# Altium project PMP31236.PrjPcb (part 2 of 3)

## Sheet PMP31236RevA_LS_U.SchDoc
size 431 x 279 mm; Date: Not shown in title block; ApprovedBy: Not shown in title block; CheckedBy: Not shown in title block; Author: Not shown in title block; CompanyName: Not shown in title block; Engineer: Not shown in title block; Organization: Not shown in title block; Address1: Not shown in title block; Address2: Not shown in title block; Address3: Not shown in title block; Address4: Not shown in title block; DocumentNumber: 4; Revision: Use project parameter SCH_Rev; SheetNumber: 4; SheetTotal: 11; PageSetup: Record=PageOptions¦CenterHorizontal=True¦CenterVertical=True¦PrintScale=1.00¦XCorrection=1.00¦YCorrection=1.00¦PrintKind=0¦BorderSize=5000000¦LeftOffset=0¦BottomOffset=0¦Orientation=2¦PaperLength=1000¦PaperWidth=1000¦Scale=100¦PaperSource=15¦PrintQuality=600¦MediaType=1¦DitherType=10¦PaperKind=Letter¦PrintScaleMode=1
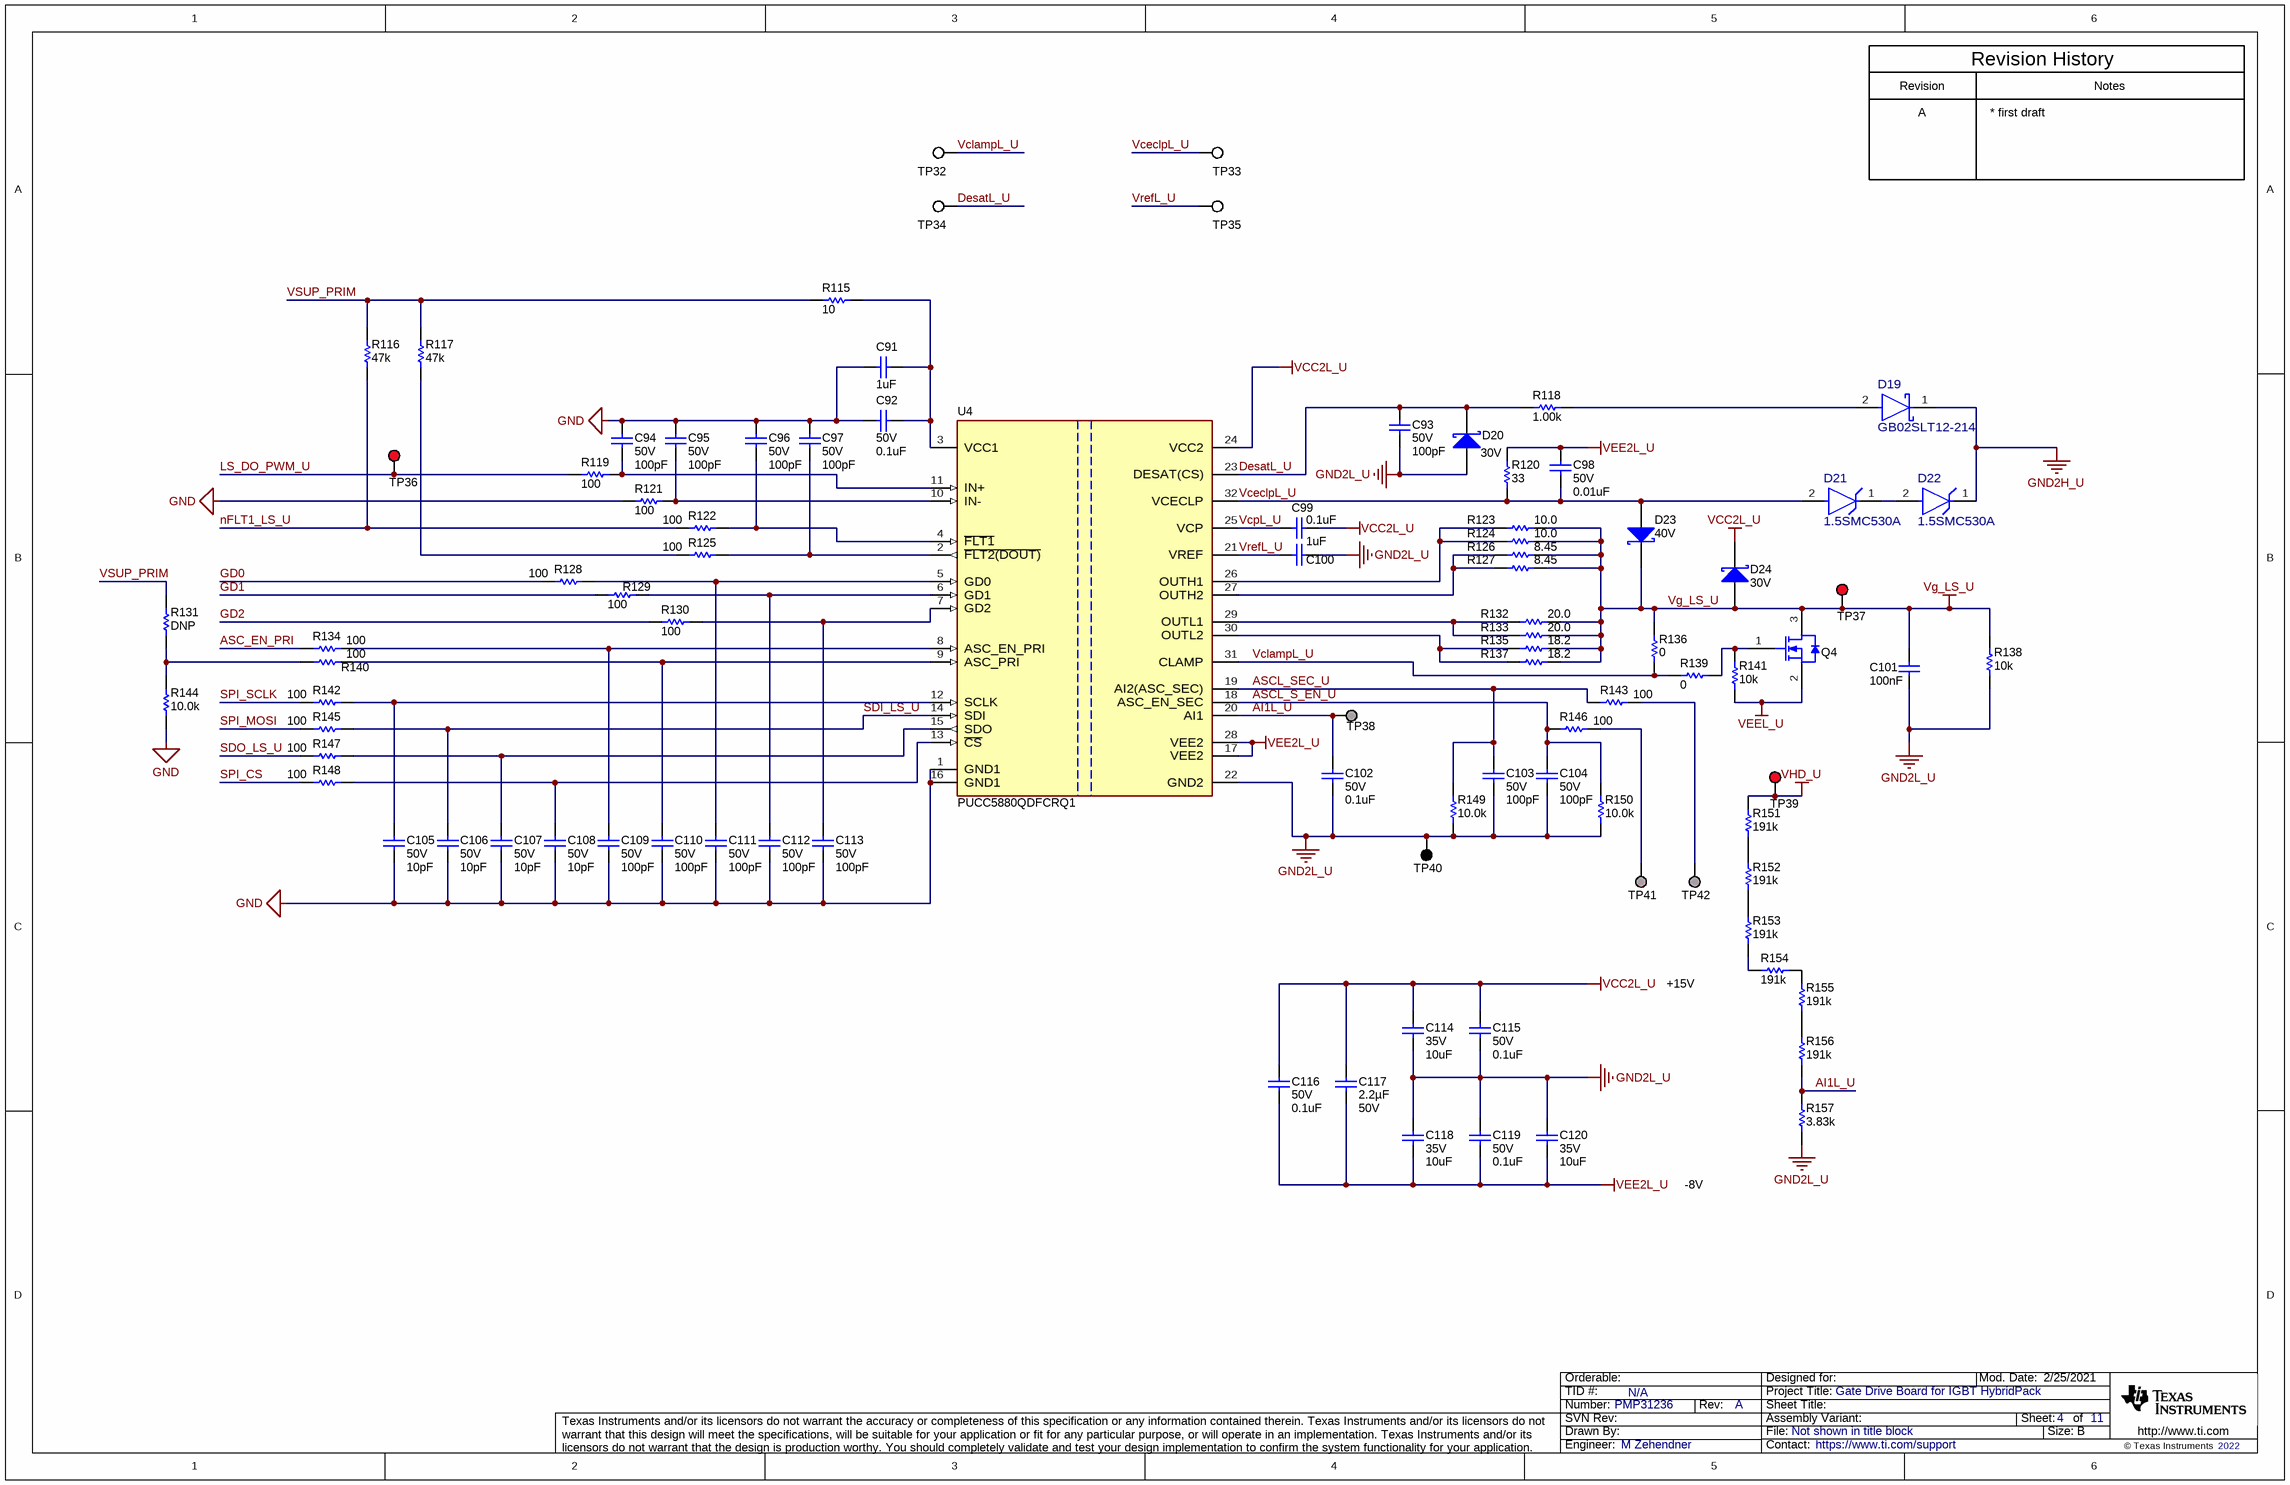
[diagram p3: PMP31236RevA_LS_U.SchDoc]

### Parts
C91  ValueDisplayed: 1uF  [0603]  (hidden comment: GRM21BR72A104KAC4L)
C92  VDC_V: 50V  ValueDisplayed: 0.1uF  [0402]  (hidden comment: GCM155R71H104KE02D)
C93  VDC_V: 50V  ValueDisplayed: 100pF  [0402]  (hidden comment: GRM1555C1H101JA01D)
C94  VDC_V: 50V  ValueDisplayed: 100pF  [0402]  (hidden comment: GRM1555C1H101JA01D)
C95  VDC_V: 50V  ValueDisplayed: 100pF  [0402]  (hidden comment: GRM1555C1H101JA01D)
C96  VDC_V: 50V  ValueDisplayed: 100pF  [0402]  (hidden comment: GRM1555C1H101JA01D)
C97  VDC_V: 50V  ValueDisplayed: 100pF  [0402]  (hidden comment: GRM1555C1H101JA01D)
C98  VDC_V: 50V  ValueDisplayed: 0.01uF  [0402]  (hidden comment: CGA2B3X7R1H103K050BB)
C99  ValueDisplayed: 0.1uF  [0402]  (hidden comment: GCM155R71H104KE02D)
C100  ValueDisplayed: 1uF  [0603]  (hidden comment: CGA3E1X7R1V105K080AC)
C101  Cap_F: 100nF  [0805_HV]  (hidden comment: C0805C104K5RACAUTO)
C102  VDC_V: 50V  ValueDisplayed: 0.1uF  [0402]  (hidden comment: GCM155R71H104KE02D)
C103  VDC_V: 50V  ValueDisplayed: 100pF  [0402]  (hidden comment: GRM1555C1H101JA01D)
C104  VDC_V: 50V  ValueDisplayed: 100pF  [0402]  (hidden comment: GRM1555C1H101JA01D)
C105  VDC_V: 50V  ValueDisplayed: 10pF  [0402]  (hidden comment: GCM1555C1H100JA16D)
C106  VDC_V: 50V  ValueDisplayed: 10pF  [0402]  (hidden comment: GCM1555C1H100JA16D)
C107  VDC_V: 50V  ValueDisplayed: 10pF  [0402]  (hidden comment: GCM1555C1H100JA16D)
C108  VDC_V: 50V  ValueDisplayed: 10pF  [0402]  (hidden comment: GCM1555C1H100JA16D)
C109  VDC_V: 50V  ValueDisplayed: 100pF  [0402]  (hidden comment: GRM1555C1H101JA01D)
C110  VDC_V: 50V  ValueDisplayed: 100pF  [0402]  (hidden comment: GRM1555C1H101JA01D)
C111  VDC_V: 50V  ValueDisplayed: 100pF  [0402]  (hidden comment: GRM1555C1H101JA01D)
C112  VDC_V: 50V  ValueDisplayed: 100pF  [0402]  (hidden comment: GRM1555C1H101JA01D)
C113  VDC_V: 50V  ValueDisplayed: 100pF  [0402]  (hidden comment: GRM1555C1H101JA01D)
C114  VDC_V: 35V  ValueDisplayed: 10uF  [1206_190]  (hidden comment: CGA5L1X7R1V106M160AC)
C115  VDC_V: 50V  ValueDisplayed: 0.1uF  [0402]  (hidden comment: GCM155R71H104KE02D)
C116  VDC_V: 50V  ValueDisplayed: 0.1uF  [0402]  (hidden comment: GCM155R71H104KE02D)
C117  Cap_F: 2.2µF  VDC_V: 50V  [0805_HV]  (hidden comment: CGA4J3X7R1H225K125AB)
C118  VDC_V: 35V  ValueDisplayed: 10uF  [1206_190]  (hidden comment: CGA5L1X7R1V106M160AC)
C119  VDC_V: 50V  ValueDisplayed: 0.1uF  [0402]  (hidden comment: GCM155R71H104KE02D)
C120  VDC_V: 35V  ValueDisplayed: 10uF  [1206_190]  (hidden comment: CGA5L1X7R1V106M160AC)
D19  GB02SLT12-214  [FP-GB02SLT12-214_DO-214AA-MFG]
D20  value 30V  [SOD-323]  (hidden comment: BAT54WS-7-F)
D21  1.5SMC530A  [FP-1.5SMC530A_SMC-MFG]
D22  1.5SMC530A  [FP-1.5SMC530A_SMC-MFG]
D23  value 40V  [SMA]  (hidden comment: MBRA340T3G)
D24  value 30V  [SOD-323]  (hidden comment: BAT54WS-7-F)
Q4  SI2318CDS-T1-GE3  [SOT-23]  (value not drawn)
R115  ValueDisplayed: 10  [0402]  (hidden comment: CRCW040210R0JNED)
R116  ValueDisplayed: 47k  [0402]  (hidden comment: CRCW040247K0JNED)
R117  ValueDisplayed: 47k  [0402]  (hidden comment: CRCW040247K0JNED)
R118  ValueDisplayed: 1.00k  [0603]  (hidden comment: CRCW06031K00FKEA)
R119  ValueDisplayed: 100  [0402]  (hidden comment: CRCW0402100RJNED)
R120  ValueDisplayed: 33  [0603]  (hidden comment: CRCW060333R0JNEA)
R121  ValueDisplayed: 100  [0402]  (hidden comment: CRCW0402100RJNED)
R122  ValueDisplayed: 100  [0402]  (hidden comment: CRCW0402100RJNED)
R123  ValueDisplayed: 10.0  [0805_HV]  (hidden comment: CRCW080510R0FKEA)
R124  ValueDisplayed: 10.0  [0805_HV]  (hidden comment: CRCW080510R0FKEA)
R125  ValueDisplayed: 100  [0402]  (hidden comment: CRCW0402100RJNED)
R126  ValueDisplayed: 8.45  [0805_HV]  (hidden comment: CRCW08058R45FKEA)
R127  ValueDisplayed: 8.45  [0805_HV]  (hidden comment: CRCW08058R45FKEA)
R128  ValueDisplayed: 100  [0402]  (hidden comment: CRCW0402100RJNED)
R129  ValueDisplayed: 100  [0402]  (hidden comment: CRCW0402100RJNED)
R130  ValueDisplayed: 100  [0402]  (hidden comment: CRCW0402100RJNED)
R131  ValueDisplayed: DNP  [0402]  (hidden comment: CRCW040210K0FKED)
R132  ValueDisplayed: 20.0  [0805_HV]  (hidden comment: CRCW080520R0FKEA)
R133  ValueDisplayed: 20.0  [0805_HV]  (hidden comment: CRCW080520R0FKEA)
R134  ValueDisplayed: 100  [0402]  (hidden comment: CRCW0402100RJNED)
R135  ValueDisplayed: 18.2  [0805_HV]  (hidden comment: CRCW080518R2FKEA)
R136  ValueDisplayed: 0  [0603]  (hidden comment: CRCW06030000Z0EA)
R137  ValueDisplayed: 18.2  [0805_HV]  (hidden comment: CRCW080518R2FKEA)
R138  ValueDisplayed: 10k  [0603]  (hidden comment: CRCW060310K0JNEA)
R139  ValueDisplayed: 0  [0603]  (hidden comment: CRCW06030000Z0EA)
R140  ValueDisplayed: 100  [0402]  (hidden comment: CRCW0402100RJNED)
R141  ValueDisplayed: 10k  [0603]  (hidden comment: CRCW060310K0JNEA)
R142  ValueDisplayed: 100  [0402]  (hidden comment: CRCW0402100RJNED)
R143  ValueDisplayed: 100  [0402]  (hidden comment: CRCW0402100RFKED)
R144  ValueDisplayed: 10.0k  [0402]  (hidden comment: CRCW040210K0FKED)
R145  ValueDisplayed: 100  [0402]  (hidden comment: CRCW0402100RJNED)
R146  ValueDisplayed: 100  [0402]  (hidden comment: CRCW0402100RFKED)
R147  ValueDisplayed: 100  [0402]  (hidden comment: CRCW0402100RJNED)
R148  ValueDisplayed: 100  [0402]  (hidden comment: CRCW0402100RJNED)
R149  ValueDisplayed: 10.0k  [0402]  (hidden comment: CRCW040210K0FKED)
R150  ValueDisplayed: 10.0k  [0402]  (hidden comment: CRCW040210K0FKED)
R151  ValueDisplayed: 191k  [1206]  (hidden comment: CRCW1206191KFKEA)
R152  ValueDisplayed: 191k  [1206]  (hidden comment: CRCW1206191KFKEA)
R153  ValueDisplayed: 191k  [1206]  (hidden comment: CRCW1206191KFKEA)
R154  ValueDisplayed: 191k  [1206]  (hidden comment: CRCW1206191KFKEA)
R155  ValueDisplayed: 191k  [1206]  (hidden comment: CRCW1206191KFKEA)
R156  ValueDisplayed: 191k  [1206]  (hidden comment: CRCW1206191KFKEA)
R157  ValueDisplayed: 3.83k  [0402]  (hidden comment: CRCW04023K83FKED)
TP32  (no value)  [Keystone5002]
TP33  (no value)  [Keystone5002]
TP34  (no value)  [Keystone5002]
TP35  (no value)  [Keystone5002]
TP36  5000  [Keystone5000]  (value not drawn)
TP37  5000  [Keystone5000]  (value not drawn)
TP38  TP_SM_1MM  [TP_SM_1MM]  (value not drawn)  (no BOM)
TP39  5000  [Keystone5000]  (value not drawn)
TP40  5001  [Keystone5001]  (value not drawn)
TP41  TP_SM_1MM  [TP_SM_1MM]  (value not drawn)  (no BOM)
TP42  TP_SM_1MM  [TP_SM_1MM]  (value not drawn)  (no BOM)
U4  PUCC5880QDFCRQ1  [DFC0032A-MFG]

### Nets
GND: C91.2 C92.1 C94.1 C95.1 C96.1 C97.1 C105.2 C106.2 C107.2 C108.2 C109.2 C110.2 C111.2 C112.2 C113.2 R121.1 R144.1 U4.1(GND1) U4.16(GND1)
GND2H_U: D19.1(CATHODE) D22.1(CATHODE)
GND2L_U: C93.2 C100.2 C101.2 C102.2 C103.2 C104.2 C114.2 C115.2 C118.1 C119.1 C120.1 D20.2(A) R138.1 R149.1 R150.1 R157.1 TP40.1 U4.22(GND2)
VCC2L_U: C99.2 C114.1 C115.1 C116.1 C117.1 D24.1(K) U4.24(VCC2)
VEE2L_U: C98.1 C116.2 C117.2 C118.2 C119.2 C120.2 R120.2 U4.17(VEE2) U4.28(VEE2)
VEEL_U: Q4.2(S) R141.1
Vg_LS_U: C101.1 D23.1(K) D24.2(A) Q4.3(D) R123.2 R124.2 R126.2 R127.2 R132.2 R133.2 R135.2 R136.2 R137.2 R138.2 TP37.1
VHD_U: R151.2 TP39.1
AI1L_U: C102.1 R156.1 R157.2 TP38.1 U4.20(AI1)
ASC_EN_PRI: R134.1
ASCL_S_EN_U: C104.1 R146.1 R150.2 U4.18(ASC_EN_SEC)
ASCL_SEC_U: C103.1 R143.1 R149.2 U4.19(AI2(ASC_SEC))
DesatL_U: C93.1 D20.1(K) R118.1 TP34.1 U4.23(DESAT(CS))
GD0: R128.1
GD1: R129.1
GD2: R130.1
LS_DO_PWM_U: R119.1 TP36.1
nFLT1_LS_U: R116.1 R122.1
SDI_LS_U: C106.1 R145.2 U4.14(SDI)
SDO_LS_U: R147.1
SPI_CS: R148.1
SPI_MOSI: R145.1
SPI_SCLK: R142.1
VceclpL_U: C98.2 D21.2(ANODE) D23.2(A) R120.1 TP33.1 U4.32(VCECLP)
VclampL_U: R136.1 R139.2 TP32.1 U4.31(CLAMP)
VcpL_U: C99.1 U4.25(VCP)
VrefL_U: C100.1 TP35.1 U4.21(VREF)
VSUP_PRIM: R115.1 R116.2 R117.2 R131.2
NetC91_1: C91.1 C92.2 R115.2 U4.3(VCC1)
NetC94_2: C94.2 R119.2 U4.11(IN+)
NetC95_2: C95.2 R121.2 U4.10(IN-)
NetC96_2: C96.2 R122.2 U4.4(~{FLT1})
NetC97_2: C97.2 R125.2 U4.2(~{FLT2(DOUT)})
NetC105_1: C105.1 R142.2 U4.12(SCLK)
NetC107_1: C107.1 R147.2 U4.15(SDO)
NetC108_1: C108.1 R148.2 U4.13(~{CS})
NetC109_1: C109.1 R134.2 U4.8(ASC_EN_PRI)
NetC110_1: C110.1 R140.2 U4.9(ASC_PRI)
NetC111_1: C111.1 R128.2 U4.5(GD0)
NetC112_1: C112.1 R129.2 U4.6(GD1)
NetC113_1: C113.1 R130.2 U4.7(GD2)
NetD19_2: D19.2(ANODE) R118.2
NetD21_1: D21.1(CATHODE) D22.2(ANODE)
NetQ4_1: Q4.1(G) R139.1 R141.2
NetR117_1: R117.1 R125.1
NetR123_1: R123.1 R124.1 U4.26(OUTH1)
NetR126_1: R126.1 R127.1 U4.27(OUTH2)
NetR131_1: R131.1 R140.1 R144.2
NetR132_1: R132.1 R133.1 U4.29(OUTL1)
NetR135_1: R135.1 R137.1 U4.30(OUTL2)
NetR143_2: R143.2 TP42.1
NetR146_2: R146.2 TP41.1
NetR151_1: R151.1 R152.2
NetR152_1: R152.1 R153.2
NetR153_1: R153.1 R154.2
NetR154_1: R154.1 R155.2
NetR155_1: R155.1 R156.2

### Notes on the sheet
- Revision
- Revision History
- Notes
- A
- * first draft
- +15V
- -8V

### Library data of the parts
C91 = CMP-0007067-4: CAP, CERM, 1 uF, 35 V, +/- 10%, X7R, AEC-Q200 Grade 1, 0603; Manufacturer: TDK; PartNumber: CGA3E1X7R1V105K080AC; TaMin_C: -55°C; ESR_ohm: 5.522m; Polarized: N; SizeAreaWB_mm2: 4.68; Value1: 0.005522 ohm; U/M: EA; Value: 1uF; TaMax_C: 125°C; SizeZ_mm: 1; SizeX_mm: 1.6; SizeY_mm: 0.8; Value2: 35V; SizeArea_mm2: 1.28; CompType: Capacitor; AEC Qualified: Y; Cap_F: 1µF; IRMS_A: 2.21617A; AEC Category: Q200
C92 C102 C115 C116 C119 = CMP-0006356-2: CAP, CERM, 0.1 uF, 50 V, +/- 10%, X7R, AEC-Q200 Grade 1, 0402; Manufacturer: MuRata; TaMin_C: -55°C; Polarized: N; SizeAreaWB_mm2: 3; Value1: Unknown; U/M: EA; Value: 0.1uF; TaMax_C: 125°C; SizeZ_mm: 0.6; SizeX_mm: 1; SizeY_mm: 0.5; AEC Qualified: Y; Cap_F: 100nF; AEC Category: Q200
C93-C97 C103 C104 C109-C113 = CMP-0006410-2: CAP, CERM, 100 pF, 50 V, +/- 5%, C0G/NP0, 0402; Manufacturer: MuRata; TaMin_C: -55°C; Polarized: N; SizeAreaWB_mm2: 3; Value1: Unknown; U/M: EA; Value: 100pF; TaMax_C: 125°C; SizeZ_mm: 0.6; SizeX_mm: 1; SizeY_mm: 0.5; AEC Category: Q200
C98 = CMP-0006324-2: CAP, CERM, 0.01 uF, 50 V, +/- 10%, X7R, AEC-Q200 Grade 1, 0402; Manufacturer: TDK; TaMin_C: -55°C; ESR_ohm: 0.3331; Polarized: N; SizeAreaWB_mm2: 3; Value1: 0.333065 ohm; U/M: EA; Value: 0.01uF; TaMax_C: 125°C; SizeZ_mm: 0.6; SizeX_mm: 1; SizeY_mm: 0.5; AEC Qualified: Y; Cap_F: 10nF; IRMS_A: 323.373mA; AEC Category: Q200
C99 = CMP-0006356-2: CAP, CERM, 0.1 uF, 50 V, +/- 10%, X7R, AEC-Q200 Grade 1, 0402; Manufacturer: MuRata; TaMin_C: -55°C; Polarized: N; SizeAreaWB_mm2: 3; Value1: Unknown; U/M: EA; Value: 0.1uF; TaMax_C: 125°C; SizeZ_mm: 0.6; SizeX_mm: 1; SizeY_mm: 0.5; Value2: 50V; AEC Qualified: Y; Cap_F: 100nF; AEC Category: Q200
C100 = CMP-0007067-4: CAP, CERM, 1 uF, 35 V, +/- 10%, X7R, AEC-Q200 Grade 1, 0603; Manufacturer: TDK; TaMin_C: -55°C; ESR_ohm: 5.522m; Polarized: N; SizeAreaWB_mm2: 4.68; Value1: 0.005522 ohm; U/M: EA; Value: 1uF; TaMax_C: 125°C; SizeZ_mm: 1; SizeX_mm: 1.6; SizeY_mm: 0.8; Value2: 35V; SizeArea_mm2: 1.28; CompType: Capacitor; AEC Qualified: Y; Cap_F: 1µF; IRMS_A: 2.21617A; AEC Category: Q200
C101 = CMP-0007725-2: CAP, CERM, 0.1 uF, 50 V, +/- 10%, X7R, AEC-Q200 Grade 0, 0805; Manufacturer: Kemet; TaMin_C: -55°C; Polarized: N; SizeAreaWB_mm2: 6.75; Value1: Unknown; U/M: EA; Value: 0.1uF; TaMax_C: 125°C; SizeZ_mm: 1.45; SizeX_mm: 2; SizeY_mm: 1.25; Cap_Case: 0805; Value2: 50V; SizeArea_mm2: 2.5; AEC Qualified: Y; AEC Grade: 0; AEC Category: Q200
C105-C108 = CMP-0860290-1: CAP, CERM, 10 pF, 50 V,+/- 5%, C0G/NP0, AEC-Q200 Grade 1, 0402; Manufacturer: MuRata; TaMin_C: -55°C; AEC Grade: 1; AEC Qualified: Y; SizeAreaWB_mm2: 3; SizeZ_mm: 0.6; Value: 10pF; TaMax_C: 125°C; Polarized: N; SizeArea_mm2: 0.5; U/M: EA; AEC Category: Q200
C114 C118 C120 = CMP-0008772-2: CAP, CERM, 10 uF, 35 V, +/- 10%, X7R, AEC-Q200 Grade 1, 1206_190; Manufacturer: TDK; PartNumber: CGA5L1X7R1V106K160AC; TaMin_C: -55°C; ESR_ohm: 2.229m; Polarized: N; SizeAreaWB_mm2: 10.92; Value1: 0.002229 ohm; U/M: EA; Value: 10uF; TaMax_C: 125°C; SizeZ_mm: 1.9; SizeX_mm: 3.2; SizeY_mm: 1.6; SizeArea_mm2: 5.12; AEC Qualified: Y; Cap_F: 10µF; IRMS_A: 4.85932A; AEC Grade: 1; AEC Category: Q200
C117 = CMP-0007977-2: CAP, CERM, 2.2 uF, 50 V, +/- 10%, X7R, AEC-Q200 Grade 1, 0805; Manufacturer: TDK; TaMin_C: -55°C; ESR_ohm: 3.288m; Polarized: N; SizeAreaWB_mm2: 6.75; Value1: 0.003288 ohm; U/M: EA; Value: 2.2uF; TaMax_C: 125°C; SizeZ_mm: 1.45; SizeX_mm: 2; SizeY_mm: 1.25; Cap_Case: 0805; SizeArea_mm2: 2.5; AEC Qualified: Y; IRMS_A: 3.6003A; AEC Grade: 1; AEC Category: Q200
D19 = CMP-0095009-1: Diode Silicon Carbide Schottky 1200 V 2A (DC) Surface Mount DO-214AA; Manufacturer: GeneSiC Semiconductor; Max Surge Forward Current: 20A; ValueDisplayed: 122pF; Vf_V: 1.2kV; Peak Reverse Current: 1uA; SizeZ_mm: 2.44mm; AEC Qualified: No; TJmax_C: 175°C
D20 D24 = CMP-0028458-1: Diode, Schottky, 30 V, 0.2 A, SOD-323; Manufacturer: Diodes Inc.; Io_A: 2dA; Green_Lifecycle: Active; SizeAreaWB_mm2: 8.695; Green_REACh: Passed; Value1: 0.2A; TJmax_C: 125°C; U/M: EA; SizeZ_mm: 1; SizeX_mm: 2.7; SizeY_mm: 1.35; Vf_V: 7dV; Value2: 0.7V; SizeArea_mm2: 3.645; AEC Category: Q101
D21 D22 = CMP-0095023-1: 725V Clamp 2.1A Ipp Tvs Diode Surface Mount DO-214AB (SMCJ); Manufacturer: Littelfuse Inc; SizeZ_mm: 2.62mm; Breakdown Voltage: 503.5V; Ppk: 1.5kW; VRWM: 451V; Direction: Unidirectional; AEC Qualified: No; TJmax_C: +150°C; Number Of Channels: 1; Ipp: 2.8A
D23 = CMP-0028553-2: Diode, Schottky, 40 V, 3 A, SMA; Manufacturer: ON Semiconductor; Io_A: 3A; Green_Lifecycle: Not Set; SizeAreaWB_mm2: 37.3428; Green_REACh: Incomplete; SizeZ_mm: 2.87; SizeX_mm: 5.59; SizeY_mm: 2.92; Vf_V: 415mV; Value2: 0.415V; SizeArea_mm2: 16.3228; AEC Category: Q101; RJC_CperW: 15
Q4 = CMP-0000739-1: MOSFET, N-CH, 40 V, 5.6 A, SOT-23; Alternate Manufacturer: None; Manufacturer: Vishay-Siliconix; SizeZ_mm: 1.1; ChType: N; Value2: 5.8 nC; Value1: 0.05; VdsMax_V: 40V; SizeX_mm: 2.5; SizeY_mm: 3; Vgs_V: 20V; Value: 40V; Rdson45_ohm: 0.051; SizeArea_mm2: 7.5; AEC Category: Q101; IdsMax_A: 5.6A; SizeAreaWB_mm2: 14; U/M: EA; QgTyp_nC: 5.8
R115 = CMP-0026827-3: RES, 10, 5%, 0.063 W, AEC-Q200 Grade 0, 0402; Manufacturer: Vishay-Dale; Power_W: 63mW; TempCo: 200 ppm/C; Value_Code: 10R0; Value: 10; EIA_Code: E24; SizeX_mm: 1; SizeY_mm: 0.5; SizeZ_mm: 0.6; Value2: 0.063W; AEC Qualified: Y; VDC_V: 50V; AEC Category: Q200; AEC Grade: 0
R116 R117 = CMP-0026935-3: RES, 47 k, 5%, 0.063 W, AEC-Q200 Grade 0, 0402; Manufacturer: Vishay-Dale; Power_W: 63mW; TempCo: 200 ppm/C; Value_Code: 47k0; Value: 47k; EIA_Code: E24; SizeX_mm: 1; SizeY_mm: 0.5; SizeZ_mm: 0.6; Value2: 0.063W; AEC Qualified: Y; VDC_V: 50V; AEC Category: Q200; AEC Grade: 0
R118 = CMP-0022109-5: RES, 1.00 k, 1%, 0.1 W, AEC-Q200 Grade 0, 0603; Manufacturer: Vishay-Dale; Power_W: 100mW; TempCo: 100 ppm/C; Value_Code: 1k00; Value: 1.00k; EIA_Code: E96; Res_ohm: 1k; SizeX_mm: 1.6; SizeY_mm: 0.8; SizeZ_mm: 1; Value2: 0.1W; SizeArea_mm2: 1.28; AEC Qualified: Y; VDC_V: 75V; AEC Category: Q200; AEC Grade: 0
R119 R121 R122 R125 R128-R130 R134 R140 R142 R145 R147 R148 = CMP-0026824-2: RES, 100, 5%, 0.063 W, 0402; Manufacturer: Vishay-Dale; Power_W: 63mW; TempCo: 200 ppm/C; Value_Code: 100R; U/M: EA; Value: 100; EIA_Code: E24; SizeX_mm: 1; SizeY_mm: 0.5; SizeZ_mm: 0.6; Value2: 0.063W; VDC_V: 50V; AEC Category: Q200
R120 = CMP-0025787-4: RES, 33, 5%, 0.1 W, AEC-Q200 Grade 0, 0603; Manufacturer: Vishay-Dale; Power_W: 100mW; TempCo: 200 ppm/C; Value_Code: 33R0; Value: 33; EIA_Code: E24; SizeX_mm: 1.6; SizeY_mm: 0.8; SizeZ_mm: 1; Value2: 0.1W; SizeArea_mm2: 1.28; CompType: Resistor; AEC Qualified: Y; VDC_V: 75V; AEC Category: Q200; AEC Grade: 0
R123 R124 = CMP-0020847-3: RES, 10.0, 1%, 0.125 W, AEC-Q200 Grade 0, 0805; Manufacturer: Vishay-Dale; Power_W: 125mW; TempCo: 100 ppm/C; Value_Code: 10R0; Value: 10.0; EIA_Code: E96; Res_ohm: 10; SizeX_mm: 2; SizeY_mm: 1.25; SizeZ_mm: 1.45; Value2: 0.125W; SizeArea_mm2: 2.5; AEC Qualified: Y; VDC_V: 150V; AEC Category: Q200; AEC Grade: 0
R126 R127 = CMP-0021481-3: RES, 8.45, 1%, 0.125 W, AEC-Q200 Grade 0, 0805; Manufacturer: Vishay-Dale; Power_W: 125mW; TempCo: 100 ppm/C; Value_Code: 8R45; Value: 8.45; EIA_Code: E96; SizeX_mm: 2; SizeY_mm: 1.25; SizeZ_mm: 1.45; Value2: 0.125W; SizeArea_mm2: 2.5; AEC Qualified: Y; VDC_V: 150V; AEC Category: Q200; AEC Grade: 0
R131 R144 R149 R150 = CMP-0025958-3: RES, 10.0 k, 1%, 0.063 W, AEC-Q200 Grade 0, 0402; Manufacturer: Vishay-Dale; Power_W: 63mW; TempCo: 100 ppm/C; Value_Code: 10k0; Value: 10.0k; EIA_Code: E96; Res_ohm: 10k; SizeX_mm: 1; SizeY_mm: 0.5; SizeZ_mm: 0.6; Value2: 0.063W; AEC Qualified: Y; VDC_V: 50V; AEC Category: Q200; AEC Grade: 0
R132 R133 = CMP-0021044-3: RES, 20.0, 1%, 0.125 W, AEC-Q200 Grade 0, 0805; Manufacturer: Vishay-Dale; Power_W: 125mW; Value_Code: 20R0; TempCo: 100 ppm/C; Value: 20.0; EIA_Code: E96; Res_ohm: 20; SizeX_mm: 2; SizeY_mm: 1.25; SizeZ_mm: 1.45; Value2: 0.125W; SizeArea_mm2: 2.5; AEC Qualified: Y; VDC_V: 150V; AEC Category: Q200; AEC Grade: 0
R135 R137 = CMP-0020941-3: RES, 18.2, 1%, 0.125 W, AEC-Q200 Grade 0, 0805; Manufacturer: Vishay-Dale; Power_W: 125mW; TempCo: 100 ppm/C; Value_Code: 18R2; Value: 18.2; EIA_Code: E96; SizeX_mm: 2; SizeY_mm: 1.25; SizeZ_mm: 1.45; Value2: 0.125W; SizeArea_mm2: 2.5; AEC Qualified: Y; VDC_V: 150V; AEC Category: Q200; AEC Grade: 0
R136 R139 = CMP-0025697-4: RES, 0, 5%, 0.1 W, AEC-Q200 Grade 0, 0603; Manufacturer: Vishay-Dale; Power_W: 100mW; TempCo: 200 ppm/C; Value_Code: 0000; Value: 0; EIA_Code: E24; SizeX_mm: 1.6; SizeY_mm: 0.8; SizeZ_mm: 1; Value2: 0.1W; SizeArea_mm2: 1.28; AEC Qualified: Y; VDC_V: 75V; AEC Category: Q200
R138 = CMP-0025701-4: RES, 10 k, 5%, 0.1 W, AEC-Q200 Grade 0, 0603; Manufacturer: Vishay-Dale; Power_W: 100mW; TempCo: 200 ppm/C; Value_Code: 10k0; Value: 10k; EIA_Code: E24; SizeX_mm: 1.6; SizeY_mm: 0.8; SizeZ_mm: 1; Value2: 0.1W; SizeArea_mm2: 1.28; AEC Qualified: Y; VDC_V: 75V; AEC Category: Q200; AEC Grade: 0
R141 = CMP-0025701-4: RES, 10 k, 5%, 0.1 W, AEC-Q200 Grade 0, 0603; Manufacturer: Vishay-Dale; Power_W: 100mW; TempCo: 200 ppm/C; Value_Code: 10k0; Value: 10k; EIA_Code: E24; SizeX_mm: 1.6; SizeY_mm: 0.8; SizeZ_mm: 1; Value2: 0.1W; SizeArea_mm2: 1.28; CompType: Resistor; AEC Qualified: Y; VDC_V: 75V; AEC Category: Q200; AEC Grade: 0
R143 R146 = CMP-0025951-3: RES, 100, 1%, 0.063 W, AEC-Q200 Grade 0, 0402; Manufacturer: Vishay-Dale; Power_W: 63mW; TempCo: 100 ppm/C; Value_Code: 100R; Value: 100; EIA_Code: E96; SizeX_mm: 1; SizeY_mm: 0.5; SizeZ_mm: 0.6; Value2: 0.063W; AEC Qualified: Y; VDC_V: 50V; AEC Category: Q200; AEC Grade: 0
R151-R156 = CMP-0016679-3: RES, 191 k, 1%, 0.25 W, AEC-Q200 Grade 0, 1206; Manufacturer: Vishay-Dale; Power_W: 250mW; TempCo: 100 ppm/C; Value: 191k; EIA_Code: E96; SizeX_mm: 3.2; SizeY_mm: 1.6; SizeZ_mm: 1.35; Value2: 0.25W; SizeArea_mm2: 5.12; AEC Qualified: Y; VDC_V: 200V; AEC Category: Q200; AEC Grade: 0
R157 = CMP-0026339-2: RES, 3.83 k, 1%, 0.063 W, AEC-Q200 Grade 0, 0402; Manufacturer: Vishay-Dale; Power_W: 63mW; TempCo: 100 ppm/C; Value_Code: 3k83; Value: 3.83k; EIA_Code: E96; SizeX_mm: 1; SizeY_mm: 0.5; SizeZ_mm: 0.6; Value2: 0.063W; AEC Qualified: Y; VDC_V: 50V; AEC Category: Q200; AEC Grade: 0
TP32-TP35 = CMP-0055139-1: Test Point, Miniature, White, TH; Manufacturer: Keystone; CNHeader: FALSE; Green_Lifecycle: Active; Green_REACh: Passed; ContactFinish: Silver; CT: TRUE
TP36 TP37 TP39 = CMP-0055137-1: Test Point, Miniature, Red, TH; Manufacturer: Keystone; CNHeader: FALSE; Green_Lifecycle: Active; Green_REACh: Passed; ContactFinish: Silver; CT: TRUE
TP38 TP41 TP42 = CMP-0003825-1: 1mm Test Point, SMT; Manufacturer: Any
TP40 = CMP-0055138-1: Test Point, Miniature, Black, TH; Manufacturer: Keystone; CNHeader: FALSE; Green_Lifecycle: Active; Green_REACh: Passed; ContactFinish: Silver; CT: TRUE
U4 = CMP-0093805-2: Isolated 20-A Adjustable Gate Drive Igbt/Sic Mosfet Gate Driver With Advanced Protection Features For Automotive Applications; Manufacturer: Texas Instruments; Nominal Supply Current: 6.5-15mA; TaMax_C: +125°C; TaMin_C: -40°C; AEC Category: Q200; Rise Time: 55ns; Standoff Height: 0.1mm; Number Of Outputs: 2; AEC Grade: Grade 0; TJmax_C: +150°C; Propagation Delay: 150ns; Max Supply Voltage: 30V; Number Of Drivers: 1; SizeZ_mm: 2.65mm; Min Supply Voltage: 3V; AEC Qualified: Yes; CompType: IC

## Sheet PMP31236RevA_LS_V.SchDoc
size 431 x 279 mm; Date: Not shown in title block; ApprovedBy: Not shown in title block; CheckedBy: Not shown in title block; Author: Not shown in title block; CompanyName: Not shown in title block; Engineer: Not shown in title block; Organization: Not shown in title block; Address1: Not shown in title block; Address2: Not shown in title block; Address3: Not shown in title block; Address4: Not shown in title block; DocumentNumber: 5; Revision: Use project parameter SCH_Rev; SheetNumber: 5; SheetTotal: 11; PageSetup: Record=PageOptions¦CenterHorizontal=True¦CenterVertical=True¦PrintScale=1.00¦XCorrection=1.00¦YCorrection=1.00¦PrintKind=0¦BorderSize=5000000¦LeftOffset=0¦BottomOffset=0¦Orientation=2¦PaperLength=1000¦PaperWidth=1000¦Scale=100¦PaperSource=15¦PrintQuality=600¦MediaType=1¦DitherType=10¦PaperKind=Letter¦PrintScaleMode=1
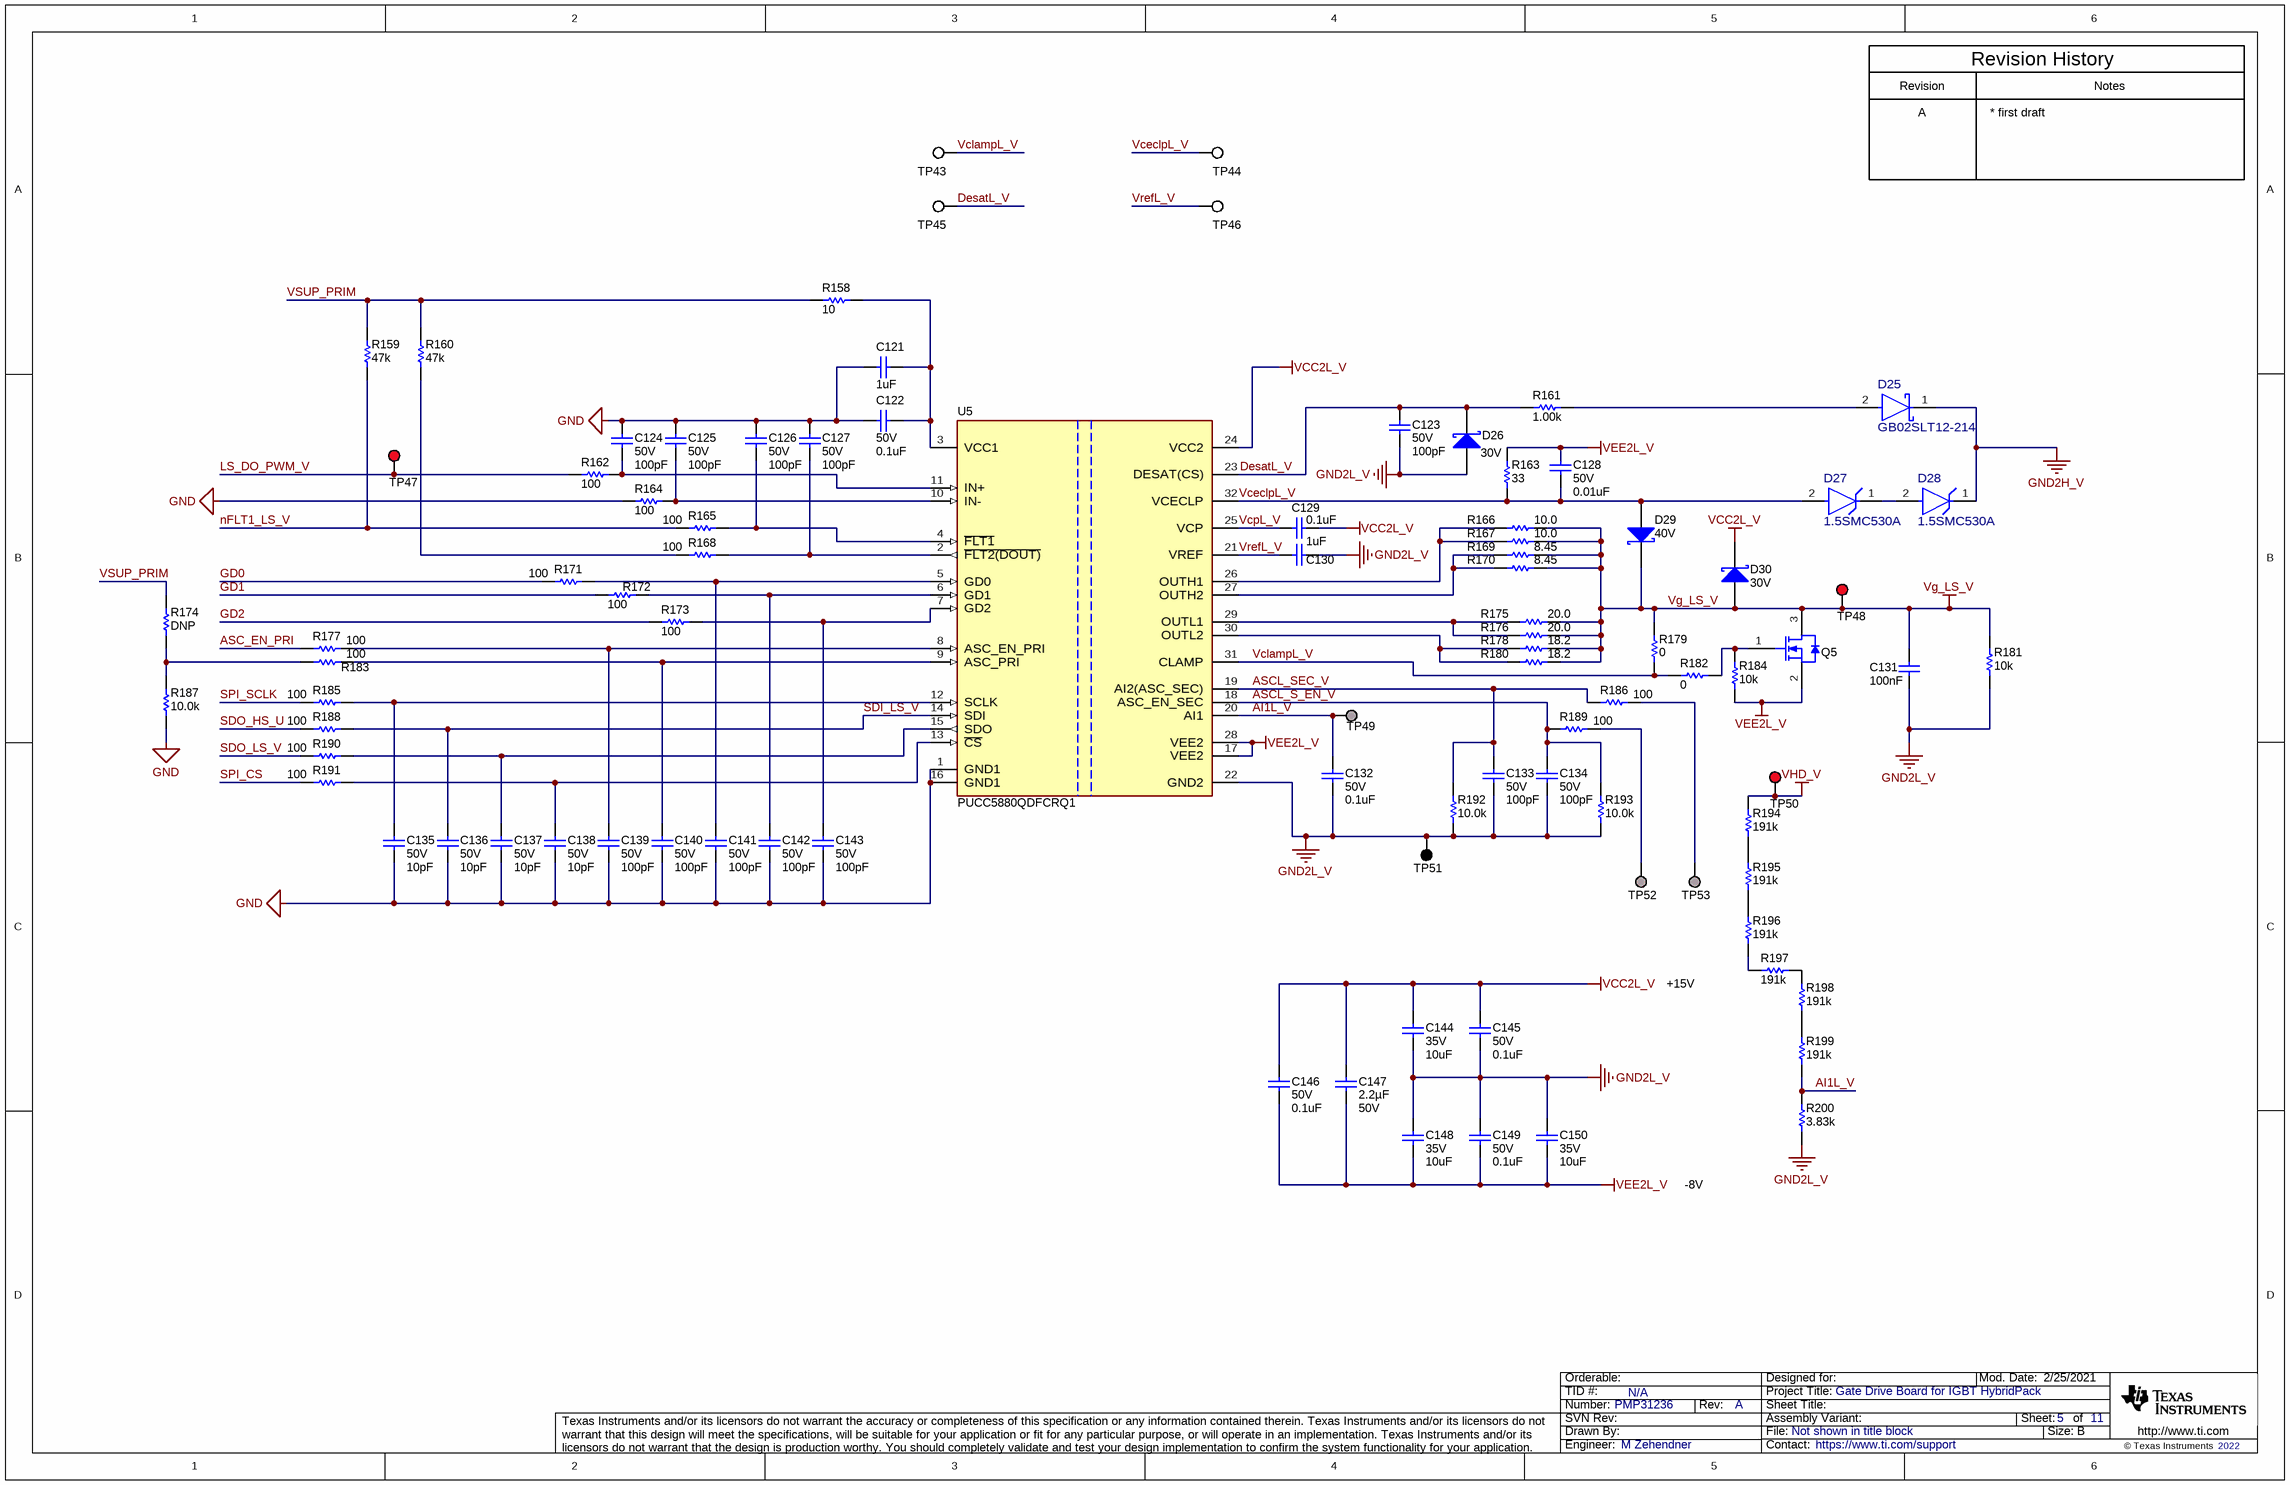
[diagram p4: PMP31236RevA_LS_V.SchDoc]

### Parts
C121  ValueDisplayed: 1uF  [0603]  (hidden comment: GRM21BR72A104KAC4L)
C122  VDC_V: 50V  ValueDisplayed: 0.1uF  [0402]  (hidden comment: GCM155R71H104KE02D)
C123  VDC_V: 50V  ValueDisplayed: 100pF  [0402]  (hidden comment: GRM1555C1H101JA01D)
C124  VDC_V: 50V  ValueDisplayed: 100pF  [0402]  (hidden comment: GRM1555C1H101JA01D)
C125  VDC_V: 50V  ValueDisplayed: 100pF  [0402]  (hidden comment: GRM1555C1H101JA01D)
C126  VDC_V: 50V  ValueDisplayed: 100pF  [0402]  (hidden comment: GRM1555C1H101JA01D)
C127  VDC_V: 50V  ValueDisplayed: 100pF  [0402]  (hidden comment: GRM1555C1H101JA01D)
C128  VDC_V: 50V  ValueDisplayed: 0.01uF  [0402]  (hidden comment: CGA2B3X7R1H103K050BB)
C129  ValueDisplayed: 0.1uF  [0402]  (hidden comment: GCM155R71H104KE02D)
C130  ValueDisplayed: 1uF  [0603]  (hidden comment: CGA3E1X7R1V105K080AC)
C131  Cap_F: 100nF  [0805_HV]  (hidden comment: C0805C104K5RACAUTO)
C132  VDC_V: 50V  ValueDisplayed: 0.1uF  [0402]  (hidden comment: GCM155R71H104KE02D)
C133  VDC_V: 50V  ValueDisplayed: 100pF  [0402]  (hidden comment: GRM1555C1H101JA01D)
C134  VDC_V: 50V  ValueDisplayed: 100pF  [0402]  (hidden comment: GRM1555C1H101JA01D)
C135  VDC_V: 50V  ValueDisplayed: 10pF  [0402]  (hidden comment: GCM1555C1H100JA16D)
C136  VDC_V: 50V  ValueDisplayed: 10pF  [0402]  (hidden comment: GCM1555C1H100JA16D)
C137  VDC_V: 50V  ValueDisplayed: 10pF  [0402]  (hidden comment: GCM1555C1H100JA16D)
C138  VDC_V: 50V  ValueDisplayed: 10pF  [0402]  (hidden comment: GCM1555C1H100JA16D)
C139  VDC_V: 50V  ValueDisplayed: 100pF  [0402]  (hidden comment: GRM1555C1H101JA01D)
C140  VDC_V: 50V  ValueDisplayed: 100pF  [0402]  (hidden comment: GRM1555C1H101JA01D)
C141  VDC_V: 50V  ValueDisplayed: 100pF  [0402]  (hidden comment: GRM1555C1H101JA01D)
C142  VDC_V: 50V  ValueDisplayed: 100pF  [0402]  (hidden comment: GRM1555C1H101JA01D)
C143  VDC_V: 50V  ValueDisplayed: 100pF  [0402]  (hidden comment: GRM1555C1H101JA01D)
C144  VDC_V: 35V  ValueDisplayed: 10uF  [1206_190]  (hidden comment: CGA5L1X7R1V106M160AC)
C145  VDC_V: 50V  ValueDisplayed: 0.1uF  [0402]  (hidden comment: GCM155R71H104KE02D)
C146  VDC_V: 50V  ValueDisplayed: 0.1uF  [0402]  (hidden comment: GCM155R71H104KE02D)
C147  Cap_F: 2.2µF  VDC_V: 50V  [0805_HV]  (hidden comment: CGA4J3X7R1H225K125AB)
C148  VDC_V: 35V  ValueDisplayed: 10uF  [1206_190]  (hidden comment: CGA5L1X7R1V106M160AC)
C149  VDC_V: 50V  ValueDisplayed: 0.1uF  [0402]  (hidden comment: GCM155R71H104KE02D)
C150  VDC_V: 35V  ValueDisplayed: 10uF  [1206_190]  (hidden comment: CGA5L1X7R1V106M160AC)
D25  GB02SLT12-214  [FP-GB02SLT12-214_DO-214AA-MFG]
D26  value 30V  [SOD-323]  (hidden comment: BAT54WS-7-F)
D27  1.5SMC530A  [FP-1.5SMC530A_SMC-MFG]
D28  1.5SMC530A  [FP-1.5SMC530A_SMC-MFG]
D29  value 40V  [SMA]  (hidden comment: MBRA340T3G)
D30  value 30V  [SOD-323]  (hidden comment: BAT54WS-7-F)
Q5  SI2318CDS-T1-GE3  [SOT-23]  (value not drawn)
R158  ValueDisplayed: 10  [0402]  (hidden comment: CRCW040210R0JNED)
R159  ValueDisplayed: 47k  [0402]  (hidden comment: CRCW040247K0JNED)
R160  ValueDisplayed: 47k  [0402]  (hidden comment: CRCW040247K0JNED)
R161  ValueDisplayed: 1.00k  [0603]  (hidden comment: CRCW06031K00FKEA)
R162  ValueDisplayed: 100  [0402]  (hidden comment: CRCW0402100RJNED)
R163  ValueDisplayed: 33  [0603]  (hidden comment: CRCW060333R0JNEA)
R164  ValueDisplayed: 100  [0402]  (hidden comment: CRCW0402100RJNED)
R165  ValueDisplayed: 100  [0402]  (hidden comment: CRCW0402100RJNED)
R166  ValueDisplayed: 10.0  [0805_HV]  (hidden comment: CRCW080510R0FKEA)
R167  ValueDisplayed: 10.0  [0805_HV]  (hidden comment: CRCW080510R0FKEA)
R168  ValueDisplayed: 100  [0402]  (hidden comment: CRCW0402100RJNED)
R169  ValueDisplayed: 8.45  [0805_HV]  (hidden comment: CRCW08058R45FKEA)
R170  ValueDisplayed: 8.45  [0805_HV]  (hidden comment: CRCW08058R45FKEA)
R171  ValueDisplayed: 100  [0402]  (hidden comment: CRCW0402100RJNED)
R172  ValueDisplayed: 100  [0402]  (hidden comment: CRCW0402100RJNED)
R173  ValueDisplayed: 100  [0402]  (hidden comment: CRCW0402100RJNED)
R174  ValueDisplayed: DNP  [0402]  (hidden comment: CRCW040210K0FKED)
R175  ValueDisplayed: 20.0  [0805_HV]  (hidden comment: CRCW080520R0FKEA)
R176  ValueDisplayed: 20.0  [0805_HV]  (hidden comment: CRCW080520R0FKEA)
R177  ValueDisplayed: 100  [0402]  (hidden comment: CRCW0402100RJNED)
R178  ValueDisplayed: 18.2  [0805_HV]  (hidden comment: CRCW080518R2FKEA)
R179  ValueDisplayed: 0  [0603]  (hidden comment: CRCW06030000Z0EA)
R180  ValueDisplayed: 18.2  [0805_HV]  (hidden comment: CRCW080518R2FKEA)
R181  ValueDisplayed: 10k  [0603]  (hidden comment: CRCW060310K0JNEA)
R182  ValueDisplayed: 0  [0603]  (hidden comment: CRCW06030000Z0EA)
R183  ValueDisplayed: 100  [0402]  (hidden comment: CRCW0402100RJNED)
R184  ValueDisplayed: 10k  [0603]  (hidden comment: CRCW060310K0JNEA)
R185  ValueDisplayed: 100  [0402]  (hidden comment: CRCW0402100RJNED)
R186  ValueDisplayed: 100  [0402]  (hidden comment: CRCW0402100RFKED)
R187  ValueDisplayed: 10.0k  [0402]  (hidden comment: CRCW040210K0FKED)
R188  ValueDisplayed: 100  [0402]  (hidden comment: CRCW0402100RJNED)
R189  ValueDisplayed: 100  [0402]  (hidden comment: CRCW0402100RFKED)
R190  ValueDisplayed: 100  [0402]  (hidden comment: CRCW0402100RJNED)
R191  ValueDisplayed: 100  [0402]  (hidden comment: CRCW0402100RJNED)
R192  ValueDisplayed: 10.0k  [0402]  (hidden comment: CRCW040210K0FKED)
R193  ValueDisplayed: 10.0k  [0402]  (hidden comment: CRCW040210K0FKED)
R194  ValueDisplayed: 191k  [1206]  (hidden comment: CRCW1206191KFKEA)
R195  ValueDisplayed: 191k  [1206]  (hidden comment: CRCW1206191KFKEA)
R196  ValueDisplayed: 191k  [1206]  (hidden comment: CRCW1206191KFKEA)
R197  ValueDisplayed: 191k  [1206]  (hidden comment: CRCW1206191KFKEA)
R198  ValueDisplayed: 191k  [1206]  (hidden comment: CRCW1206191KFKEA)
R199  ValueDisplayed: 191k  [1206]  (hidden comment: CRCW1206191KFKEA)
R200  ValueDisplayed: 3.83k  [0402]  (hidden comment: CRCW04023K83FKED)
TP43  (no value)  [Keystone5002]
TP44  (no value)  [Keystone5002]
TP45  (no value)  [Keystone5002]
TP46  (no value)  [Keystone5002]
TP47  5000  [Keystone5000]  (value not drawn)
TP48  5000  [Keystone5000]  (value not drawn)
TP49  TP_SM_1MM  [TP_SM_1MM]  (value not drawn)  (no BOM)
TP50  5000  [Keystone5000]  (value not drawn)
TP51  5001  [Keystone5001]  (value not drawn)
TP52  TP_SM_1MM  [TP_SM_1MM]  (value not drawn)  (no BOM)
TP53  TP_SM_1MM  [TP_SM_1MM]  (value not drawn)  (no BOM)
U5  PUCC5880QDFCRQ1  [DFC0032A-MFG]

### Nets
GND: C121.2 C122.1 C124.1 C125.1 C126.1 C127.1 C135.2 C136.2 C137.2 C138.2 C139.2 C140.2 C141.2 C142.2 C143.2 R164.1 R187.1 U5.1(GND1) U5.16(GND1)
GND2H_V: D25.1(CATHODE) D28.1(CATHODE)
GND2L_V: C123.2 C130.2 C131.2 C132.2 C133.2 C134.2 C144.2 C145.2 C148.1 C149.1 C150.1 D26.2(A) R181.1 R192.1 R193.1 R200.1 TP51.1 U5.22(GND2)
VCC2L_V: C129.2 C144.1 C145.1 C146.1 C147.1 D30.1(K) U5.24(VCC2)
VEE2L_V: C128.1 C146.2 C147.2 C148.2 C149.2 C150.2 Q5.2(S) R163.2 R184.1 U5.17(VEE2) U5.28(VEE2)
Vg_LS_V: C131.1 D29.1(K) D30.2(A) Q5.3(D) R166.2 R167.2 R169.2 R170.2 R175.2 R176.2 R178.2 R179.2 R180.2 R181.2 TP48.1
VHD_V: R194.2 TP50.1
AI1L_V: C132.1 R199.1 R200.2 TP49.1 U5.20(AI1)
ASC_EN_PRI: R177.1
ASCL_S_EN_V: C134.1 R189.1 R193.2 U5.18(ASC_EN_SEC)
ASCL_SEC_V: C133.1 R186.1 R192.2 U5.19(AI2(ASC_SEC))
DesatL_V: C123.1 D26.1(K) R161.1 TP45.1 U5.23(DESAT(CS))
GD0: R171.1
GD1: R172.1
GD2: R173.1
LS_DO_PWM_V: R162.1 TP47.1
nFLT1_LS_V: R159.1 R165.1
SDI_LS_V: C136.1 R188.2 U5.14(SDI)
SDO_HS_U: R188.1
SDO_LS_V: R190.1
SPI_CS: R191.1
SPI_SCLK: R185.1
VceclpL_V: C128.2 D27.2(ANODE) D29.2(A) R163.1 TP44.1 U5.32(VCECLP)
VclampL_V: R179.1 R182.2 TP43.1 U5.31(CLAMP)
VcpL_V: C129.1 U5.25(VCP)
VrefL_V: C130.1 TP46.1 U5.21(VREF)
VSUP_PRIM: R158.1 R159.2 R160.2 R174.2
NetC121_1: C121.1 C122.2 R158.2 U5.3(VCC1)
NetC124_2: C124.2 R162.2 U5.11(IN+)
NetC125_2: C125.2 R164.2 U5.10(IN-)
NetC126_2: C126.2 R165.2 U5.4(~{FLT1})
NetC127_2: C127.2 R168.2 U5.2(~{FLT2(DOUT)})
NetC135_1: C135.1 R185.2 U5.12(SCLK)
NetC137_1: C137.1 R190.2 U5.15(SDO)
NetC138_1: C138.1 R191.2 U5.13(~{CS})
NetC139_1: C139.1 R177.2 U5.8(ASC_EN_PRI)
NetC140_1: C140.1 R183.2 U5.9(ASC_PRI)
NetC141_1: C141.1 R171.2 U5.5(GD0)
NetC142_1: C142.1 R172.2 U5.6(GD1)
NetC143_1: C143.1 R173.2 U5.7(GD2)
NetD25_2: D25.2(ANODE) R161.2
NetD27_1: D27.1(CATHODE) D28.2(ANODE)
NetQ5_1: Q5.1(G) R182.1 R184.2
NetR160_1: R160.1 R168.1
NetR166_1: R166.1 R167.1 U5.26(OUTH1)
NetR169_1: R169.1 R170.1 U5.27(OUTH2)
NetR174_1: R174.1 R183.1 R187.2
NetR175_1: R175.1 R176.1 U5.29(OUTL1)
NetR178_1: R178.1 R180.1 U5.30(OUTL2)
NetR186_2: R186.2 TP53.1
NetR189_2: R189.2 TP52.1
NetR194_1: R194.1 R195.2
NetR195_1: R195.1 R196.2
NetR196_1: R196.1 R197.2
NetR197_1: R197.1 R198.2
NetR198_1: R198.1 R199.2

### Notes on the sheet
- Revision
- Revision History
- Notes
- A
- * first draft
- +15V
- -8V

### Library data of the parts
C121 = CMP-0007067-4: as C91 on sheet PMP31236RevA_LS_U
C122 C132 C145 C146 C149 = CMP-0006356-2: as C92 on sheet PMP31236RevA_LS_U
C123-C127 C133 C134 C139-C143 = CMP-0006410-2: as C93-C97 on sheet PMP31236RevA_LS_U
C128 = CMP-0006324-2: as C98 on sheet PMP31236RevA_LS_U
C129 = CMP-0006356-2: as C99 on sheet PMP31236RevA_LS_U
C130 = CMP-0007067-4: as C100 on sheet PMP31236RevA_LS_U
C131 = CMP-0007725-2: as C101 on sheet PMP31236RevA_LS_U
C135-C138 = CMP-0860290-1: as C105-C108 on sheet PMP31236RevA_LS_U
C144 C148 C150 = CMP-0008772-2: as C114 on sheet PMP31236RevA_LS_U
C147 = CMP-0007977-2: as C117 on sheet PMP31236RevA_LS_U
D25 = CMP-0095009-1: as D19 on sheet PMP31236RevA_LS_U
D26 D30 = CMP-0028458-1: as D20 on sheet PMP31236RevA_LS_U
D27 D28 = CMP-0095023-1: as D21 on sheet PMP31236RevA_LS_U
D29 = CMP-0028553-2: as D23 on sheet PMP31236RevA_LS_U
Q5 = CMP-0000739-1: as Q4 on sheet PMP31236RevA_LS_U
R158 = CMP-0026827-3: as R115 on sheet PMP31236RevA_LS_U
R159 R160 = CMP-0026935-3: as R116 on sheet PMP31236RevA_LS_U
R161 = CMP-0022109-5: as R118 on sheet PMP31236RevA_LS_U
R162 R164 R165 R168 R171-R173 R177 R183 R185 R188 R190 R191 = CMP-0026824-2: as R119 on sheet PMP31236RevA_LS_U
R163 = CMP-0025787-4: as R120 on sheet PMP31236RevA_LS_U
R166 R167 = CMP-0020847-3: as R123 on sheet PMP31236RevA_LS_U
R169 R170 = CMP-0021481-3: as R126 on sheet PMP31236RevA_LS_U
R174 R187 R192 R193 = CMP-0025958-3: as R131 on sheet PMP31236RevA_LS_U
R175 R176 = CMP-0021044-3: as R132 on sheet PMP31236RevA_LS_U
R178 R180 = CMP-0020941-3: as R135 on sheet PMP31236RevA_LS_U
R179 R182 = CMP-0025697-4: as R136 on sheet PMP31236RevA_LS_U
R181 = CMP-0025701-4: as R138 on sheet PMP31236RevA_LS_U
R184 = CMP-0025701-4: as R141 on sheet PMP31236RevA_LS_U
R186 R189 = CMP-0025951-3: as R143 on sheet PMP31236RevA_LS_U
R194-R199 = CMP-0016679-3: as R151 on sheet PMP31236RevA_LS_U
R200 = CMP-0026339-2: as R157 on sheet PMP31236RevA_LS_U
TP43-TP46 = CMP-0055139-1: as TP32-TP35 on sheet PMP31236RevA_LS_U
TP47 TP48 TP50 = CMP-0055137-1: as TP36 on sheet PMP31236RevA_LS_U
TP49 TP52 TP53 = CMP-0003825-1: 1mm Test Point, SMT; Manufacturer: Any
TP51 = CMP-0055138-1: as TP40 on sheet PMP31236RevA_LS_U
U5 = CMP-0093805-2: as U4 on sheet PMP31236RevA_LS_U

## Sheet PMP31236RevA_LS_W.SchDoc
size 431 x 279 mm; Date: Not shown in title block; ApprovedBy: Not shown in title block; CheckedBy: Not shown in title block; Author: Not shown in title block; CompanyName: Not shown in title block; Engineer: Not shown in title block; Organization: Not shown in title block; Address1: Not shown in title block; Address2: Not shown in title block; Address3: Not shown in title block; Address4: Not shown in title block; DocumentNumber: 6; Revision: Use project parameter SCH_Rev; SheetNumber: 6; SheetTotal: 11; PageSetup: Record=PageOptions¦CenterHorizontal=True¦CenterVertical=True¦PrintScale=1.00¦XCorrection=1.00¦YCorrection=1.00¦PrintKind=0¦BorderSize=5000000¦LeftOffset=0¦BottomOffset=0¦Orientation=2¦PaperLength=1000¦PaperWidth=1000¦Scale=100¦PaperSource=15¦PrintQuality=600¦MediaType=1¦DitherType=10¦PaperKind=Letter¦PrintScaleMode=1
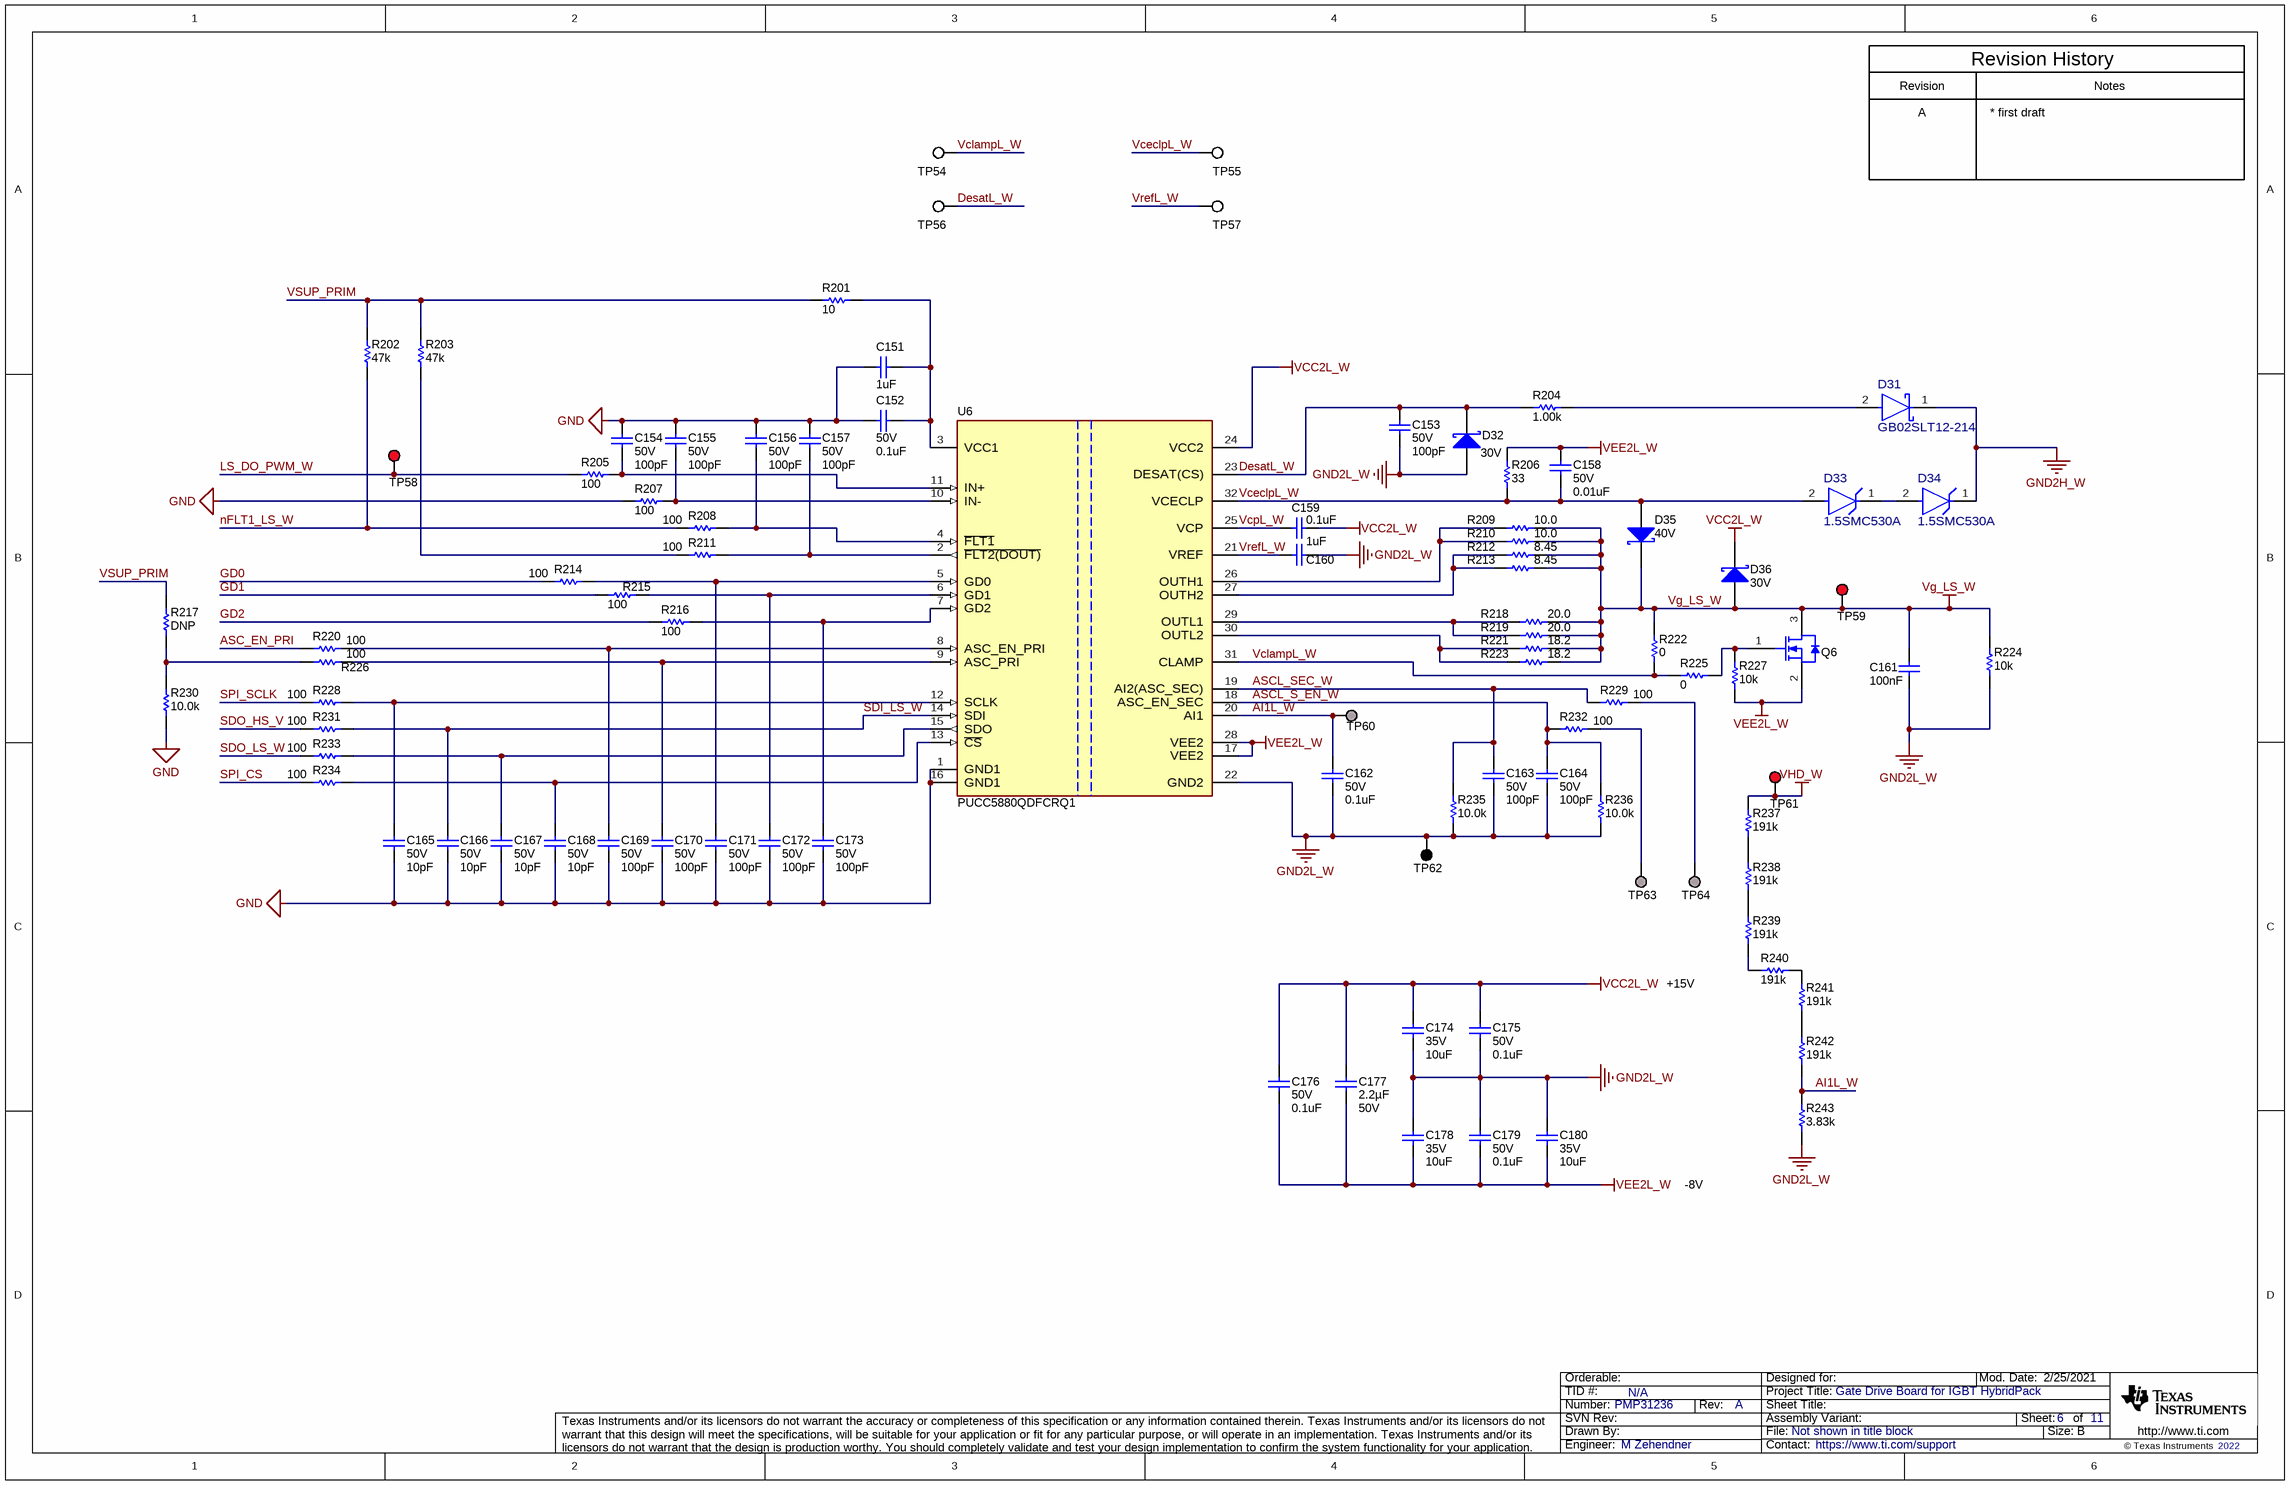
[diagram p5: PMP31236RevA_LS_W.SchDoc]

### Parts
C151  ValueDisplayed: 1uF  [0603]  (hidden comment: GRM21BR72A104KAC4L)
C152  VDC_V: 50V  ValueDisplayed: 0.1uF  [0402]  (hidden comment: GCM155R71H104KE02D)
C153  VDC_V: 50V  ValueDisplayed: 100pF  [0402]  (hidden comment: GRM1555C1H101JA01D)
C154  VDC_V: 50V  ValueDisplayed: 100pF  [0402]  (hidden comment: GRM1555C1H101JA01D)
C155  VDC_V: 50V  ValueDisplayed: 100pF  [0402]  (hidden comment: GRM1555C1H101JA01D)
C156  VDC_V: 50V  ValueDisplayed: 100pF  [0402]  (hidden comment: GRM1555C1H101JA01D)
C157  VDC_V: 50V  ValueDisplayed: 100pF  [0402]  (hidden comment: GRM1555C1H101JA01D)
C158  VDC_V: 50V  ValueDisplayed: 0.01uF  [0402]  (hidden comment: CGA2B3X7R1H103K050BB)
C159  ValueDisplayed: 0.1uF  [0402]  (hidden comment: GCM155R71H104KE02D)
C160  ValueDisplayed: 1uF  [0603]  (hidden comment: CGA3E1X7R1V105K080AC)
C161  Cap_F: 100nF  [0805_HV]  (hidden comment: C0805C104K5RACAUTO)
C162  VDC_V: 50V  ValueDisplayed: 0.1uF  [0402]  (hidden comment: GCM155R71H104KE02D)
C163  VDC_V: 50V  ValueDisplayed: 100pF  [0402]  (hidden comment: GRM1555C1H101JA01D)
C164  VDC_V: 50V  ValueDisplayed: 100pF  [0402]  (hidden comment: GRM1555C1H101JA01D)
C165  VDC_V: 50V  ValueDisplayed: 10pF  [0402]  (hidden comment: GCM1555C1H100JA16D)
C166  VDC_V: 50V  ValueDisplayed: 10pF  [0402]  (hidden comment: GCM1555C1H100JA16D)
C167  VDC_V: 50V  ValueDisplayed: 10pF  [0402]  (hidden comment: GCM1555C1H100JA16D)
C168  VDC_V: 50V  ValueDisplayed: 10pF  [0402]  (hidden comment: GCM1555C1H100JA16D)
C169  VDC_V: 50V  ValueDisplayed: 100pF  [0402]  (hidden comment: GRM1555C1H101JA01D)
C170  VDC_V: 50V  ValueDisplayed: 100pF  [0402]  (hidden comment: GRM1555C1H101JA01D)
C171  VDC_V: 50V  ValueDisplayed: 100pF  [0402]  (hidden comment: GRM1555C1H101JA01D)
C172  VDC_V: 50V  ValueDisplayed: 100pF  [0402]  (hidden comment: GRM1555C1H101JA01D)
C173  VDC_V: 50V  ValueDisplayed: 100pF  [0402]  (hidden comment: GRM1555C1H101JA01D)
C174  VDC_V: 35V  ValueDisplayed: 10uF  [1206_190]  (hidden comment: CGA5L1X7R1V106M160AC)
C175  VDC_V: 50V  ValueDisplayed: 0.1uF  [0402]  (hidden comment: GCM155R71H104KE02D)
C176  VDC_V: 50V  ValueDisplayed: 0.1uF  [0402]  (hidden comment: GCM155R71H104KE02D)
C177  Cap_F: 2.2µF  VDC_V: 50V  [0805_HV]  (hidden comment: CGA4J3X7R1H225K125AB)
C178  VDC_V: 35V  ValueDisplayed: 10uF  [1206_190]  (hidden comment: CGA5L1X7R1V106M160AC)
C179  VDC_V: 50V  ValueDisplayed: 0.1uF  [0402]  (hidden comment: GCM155R71H104KE02D)
C180  VDC_V: 35V  ValueDisplayed: 10uF  [1206_190]  (hidden comment: CGA5L1X7R1V106M160AC)
D31  GB02SLT12-214  [FP-GB02SLT12-214_DO-214AA-MFG]
D32  value 30V  [SOD-323]  (hidden comment: BAT54WS-7-F)
D33  1.5SMC530A  [FP-1.5SMC530A_SMC-MFG]
D34  1.5SMC530A  [FP-1.5SMC530A_SMC-MFG]
D35  value 40V  [SMA]  (hidden comment: MBRA340T3G)
D36  value 30V  [SOD-323]  (hidden comment: BAT54WS-7-F)
Q6  SI2318CDS-T1-GE3  [SOT-23]  (value not drawn)
R201  ValueDisplayed: 10  [0402]  (hidden comment: CRCW040210R0JNED)
R202  ValueDisplayed: 47k  [0402]  (hidden comment: CRCW040247K0JNED)
R203  ValueDisplayed: 47k  [0402]  (hidden comment: CRCW040247K0JNED)
R204  ValueDisplayed: 1.00k  [0603]  (hidden comment: CRCW06031K00FKEA)
R205  ValueDisplayed: 100  [0402]  (hidden comment: CRCW0402100RJNED)
R206  ValueDisplayed: 33  [0603]  (hidden comment: CRCW060333R0JNEA)
R207  ValueDisplayed: 100  [0402]  (hidden comment: CRCW0402100RJNED)
R208  ValueDisplayed: 100  [0402]  (hidden comment: CRCW0402100RJNED)
R209  ValueDisplayed: 10.0  [0805_HV]  (hidden comment: CRCW080510R0FKEA)
R210  ValueDisplayed: 10.0  [0805_HV]  (hidden comment: CRCW080510R0FKEA)
R211  ValueDisplayed: 100  [0402]  (hidden comment: CRCW0402100RJNED)
R212  ValueDisplayed: 8.45  [0805_HV]  (hidden comment: CRCW08058R45FKEA)
R213  ValueDisplayed: 8.45  [0805_HV]  (hidden comment: CRCW08058R45FKEA)
R214  ValueDisplayed: 100  [0402]  (hidden comment: CRCW0402100RJNED)
R215  ValueDisplayed: 100  [0402]  (hidden comment: CRCW0402100RJNED)
R216  ValueDisplayed: 100  [0402]  (hidden comment: CRCW0402100RJNED)
R217  ValueDisplayed: DNP  [0402]  (hidden comment: CRCW040210K0FKED)
R218  ValueDisplayed: 20.0  [0805_HV]  (hidden comment: CRCW080520R0FKEA)
R219  ValueDisplayed: 20.0  [0805_HV]  (hidden comment: CRCW080520R0FKEA)
R220  ValueDisplayed: 100  [0402]  (hidden comment: CRCW0402100RJNED)
R221  ValueDisplayed: 18.2  [0805_HV]  (hidden comment: CRCW080518R2FKEA)
R222  ValueDisplayed: 0  [0603]  (hidden comment: CRCW06030000Z0EA)
R223  ValueDisplayed: 18.2  [0805_HV]  (hidden comment: CRCW080518R2FKEA)
R224  ValueDisplayed: 10k  [0603]  (hidden comment: CRCW060310K0JNEA)
R225  ValueDisplayed: 0  [0603]  (hidden comment: CRCW06030000Z0EA)
R226  ValueDisplayed: 100  [0402]  (hidden comment: CRCW0402100RJNED)
R227  ValueDisplayed: 10k  [0603]  (hidden comment: CRCW060310K0JNEA)
R228  ValueDisplayed: 100  [0402]  (hidden comment: CRCW0402100RJNED)
R229  ValueDisplayed: 100  [0402]  (hidden comment: CRCW0402100RFKED)
R230  ValueDisplayed: 10.0k  [0402]  (hidden comment: CRCW040210K0FKED)
R231  ValueDisplayed: 100  [0402]  (hidden comment: CRCW0402100RJNED)
R232  ValueDisplayed: 100  [0402]  (hidden comment: CRCW0402100RFKED)
R233  ValueDisplayed: 100  [0402]  (hidden comment: CRCW0402100RJNED)
R234  ValueDisplayed: 100  [0402]  (hidden comment: CRCW0402100RJNED)
R235  ValueDisplayed: 10.0k  [0402]  (hidden comment: CRCW040210K0FKED)
R236  ValueDisplayed: 10.0k  [0402]  (hidden comment: CRCW040210K0FKED)
R237  ValueDisplayed: 191k  [1206]  (hidden comment: CRCW1206191KFKEA)
R238  ValueDisplayed: 191k  [1206]  (hidden comment: CRCW1206191KFKEA)
R239  ValueDisplayed: 191k  [1206]  (hidden comment: CRCW1206191KFKEA)
R240  ValueDisplayed: 191k  [1206]  (hidden comment: CRCW1206191KFKEA)
R241  ValueDisplayed: 191k  [1206]  (hidden comment: CRCW1206191KFKEA)
R242  ValueDisplayed: 191k  [1206]  (hidden comment: CRCW1206191KFKEA)
R243  ValueDisplayed: 3.83k  [0402]  (hidden comment: CRCW04023K83FKED)
TP54  (no value)  [Keystone5002]
TP55  (no value)  [Keystone5002]
TP56  (no value)  [Keystone5002]
TP57  (no value)  [Keystone5002]
TP58  5000  [Keystone5000]  (value not drawn)
TP59  5000  [Keystone5000]  (value not drawn)
TP60  TP_SM_1MM  [TP_SM_1MM]  (value not drawn)  (no BOM)
TP61  5000  [Keystone5000]  (value not drawn)
TP62  5001  [Keystone5001]  (value not drawn)
TP63  TP_SM_1MM  [TP_SM_1MM]  (value not drawn)  (no BOM)
TP64  TP_SM_1MM  [TP_SM_1MM]  (value not drawn)  (no BOM)
U6  PUCC5880QDFCRQ1  [DFC0032A-MFG]

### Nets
GND: C151.2 C152.1 C154.1 C155.1 C156.1 C157.1 C165.2 C166.2 C167.2 C168.2 C169.2 C170.2 C171.2 C172.2 C173.2 R207.1 R230.1 U6.1(GND1) U6.16(GND1)
GND2H_W: D31.1(CATHODE) D34.1(CATHODE)
GND2L_W: C153.2 C160.2 C161.2 C162.2 C163.2 C164.2 C174.2 C175.2 C178.1 C179.1 C180.1 D32.2(A) R224.1 R235.1 R236.1 R243.1 TP62.1 U6.22(GND2)
VCC2L_W: C159.2 C174.1 C175.1 C176.1 C177.1 D36.1(K) U6.24(VCC2)
VEE2L_W: C158.1 C176.2 C177.2 C178.2 C179.2 C180.2 Q6.2(S) R206.2 R227.1 U6.17(VEE2) U6.28(VEE2)
Vg_LS_W: C161.1 D35.1(K) D36.2(A) Q6.3(D) R209.2 R210.2 R212.2 R213.2 R218.2 R219.2 R221.2 R222.2 R223.2 R224.2 TP59.1
VHD_W: R237.2 TP61.1
AI1L_W: C162.1 R242.1 R243.2 TP60.1 U6.20(AI1)
ASC_EN_PRI: R220.1
ASCL_S_EN_W: C164.1 R232.1 R236.2 U6.18(ASC_EN_SEC)
ASCL_SEC_W: C163.1 R229.1 R235.2 U6.19(AI2(ASC_SEC))
DesatL_W: C153.1 D32.1(K) R204.1 TP56.1 U6.23(DESAT(CS))
GD0: R214.1
GD1: R215.1
GD2: R216.1
LS_DO_PWM_W: R205.1 TP58.1
nFLT1_LS_W: R202.1 R208.1
SDI_LS_W: C166.1 R231.2 U6.14(SDI)
SDO_HS_V: R231.1
SDO_LS_W: R233.1
SPI_CS: R234.1
SPI_SCLK: R228.1
VceclpL_W: C158.2 D33.2(ANODE) D35.2(A) R206.1 TP55.1 U6.32(VCECLP)
VclampL_W: R222.1 R225.2 TP54.1 U6.31(CLAMP)
VcpL_W: C159.1 U6.25(VCP)
VrefL_W: C160.1 TP57.1 U6.21(VREF)
VSUP_PRIM: R201.1 R202.2 R203.2 R217.2
NetC151_1: C151.1 C152.2 R201.2 U6.3(VCC1)
NetC154_2: C154.2 R205.2 U6.11(IN+)
NetC155_2: C155.2 R207.2 U6.10(IN-)
NetC156_2: C156.2 R208.2 U6.4(~{FLT1})
NetC157_2: C157.2 R211.2 U6.2(~{FLT2(DOUT)})
NetC165_1: C165.1 R228.2 U6.12(SCLK)
NetC167_1: C167.1 R233.2 U6.15(SDO)
NetC168_1: C168.1 R234.2 U6.13(~{CS})
NetC169_1: C169.1 R220.2 U6.8(ASC_EN_PRI)
NetC170_1: C170.1 R226.2 U6.9(ASC_PRI)
NetC171_1: C171.1 R214.2 U6.5(GD0)
NetC172_1: C172.1 R215.2 U6.6(GD1)
NetC173_1: C173.1 R216.2 U6.7(GD2)
NetD31_2: D31.2(ANODE) R204.2
NetD33_1: D33.1(CATHODE) D34.2(ANODE)
NetQ6_1: Q6.1(G) R225.1 R227.2
NetR203_1: R203.1 R211.1
NetR209_1: R209.1 R210.1 U6.26(OUTH1)
NetR212_1: R212.1 R213.1 U6.27(OUTH2)
NetR217_1: R217.1 R226.1 R230.2
NetR218_1: R218.1 R219.1 U6.29(OUTL1)
NetR221_1: R221.1 R223.1 U6.30(OUTL2)
NetR229_2: R229.2 TP64.1
NetR232_2: R232.2 TP63.1
NetR237_1: R237.1 R238.2
NetR238_1: R238.1 R239.2
NetR239_1: R239.1 R240.2
NetR240_1: R240.1 R241.2
NetR241_1: R241.1 R242.2

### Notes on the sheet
- Revision
- Revision History
- Notes
- A
- * first draft
- +15V
- -8V

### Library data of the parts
C151 = CMP-0007067-4: as C91 on sheet PMP31236RevA_LS_U
C152 C162 C175 C176 C179 = CMP-0006356-2: as C92 on sheet PMP31236RevA_LS_U
C153-C157 C163 C164 C169-C173 = CMP-0006410-2: as C93-C97 on sheet PMP31236RevA_LS_U
C158 = CMP-0006324-2: as C98 on sheet PMP31236RevA_LS_U
C159 = CMP-0006356-2: as C99 on sheet PMP31236RevA_LS_U
C160 = CMP-0007067-4: as C100 on sheet PMP31236RevA_LS_U
C161 = CMP-0007725-2: as C101 on sheet PMP31236RevA_LS_U
C165-C168 = CMP-0860290-1: as C105-C108 on sheet PMP31236RevA_LS_U
C174 C178 C180 = CMP-0008772-2: as C114 on sheet PMP31236RevA_LS_U
C177 = CMP-0007977-2: as C117 on sheet PMP31236RevA_LS_U
D31 = CMP-0095009-1: as D19 on sheet PMP31236RevA_LS_U
D32 D36 = CMP-0028458-1: as D20 on sheet PMP31236RevA_LS_U
D33 D34 = CMP-0095023-1: as D21 on sheet PMP31236RevA_LS_U
D35 = CMP-0028553-2: as D23 on sheet PMP31236RevA_LS_U
Q6 = CMP-0000739-1: as Q4 on sheet PMP31236RevA_LS_U
R201 = CMP-0026827-3: as R115 on sheet PMP31236RevA_LS_U
R202 R203 = CMP-0026935-3: as R116 on sheet PMP31236RevA_LS_U
R204 = CMP-0022109-5: as R118 on sheet PMP31236RevA_LS_U
R205 R207 R208 R211 R214-R216 R220 R226 R228 R231 R233 R234 = CMP-0026824-2: as R119 on sheet PMP31236RevA_LS_U
R206 = CMP-0025787-4: as R120 on sheet PMP31236RevA_LS_U
R209 R210 = CMP-0020847-3: as R123 on sheet PMP31236RevA_LS_U
R212 R213 = CMP-0021481-3: as R126 on sheet PMP31236RevA_LS_U
R217 R230 R235 R236 = CMP-0025958-3: as R131 on sheet PMP31236RevA_LS_U
R218 R219 = CMP-0021044-3: as R132 on sheet PMP31236RevA_LS_U
R221 R223 = CMP-0020941-3: as R135 on sheet PMP31236RevA_LS_U
R222 R225 = CMP-0025697-4: as R136 on sheet PMP31236RevA_LS_U
R224 = CMP-0025701-4: as R138 on sheet PMP31236RevA_LS_U
R227 = CMP-0025701-4: as R141 on sheet PMP31236RevA_LS_U
R229 R232 = CMP-0025951-3: as R143 on sheet PMP31236RevA_LS_U
R237-R242 = CMP-0016679-3: as R151 on sheet PMP31236RevA_LS_U
R243 = CMP-0026339-2: as R157 on sheet PMP31236RevA_LS_U
TP54-TP57 = CMP-0055139-1: as TP32-TP35 on sheet PMP31236RevA_LS_U
TP58 TP59 TP61 = CMP-0055137-1: as TP36 on sheet PMP31236RevA_LS_U
TP60 TP63 TP64 = CMP-0003825-1: 1mm Test Point, SMT; Manufacturer: Any
TP62 = CMP-0055138-1: as TP40 on sheet PMP31236RevA_LS_U
U6 = CMP-0093805-2: as U4 on sheet PMP31236RevA_LS_U

## Sheet PMP31236RevA_Interface.SchDoc: Interface
size A4; Date: Not shown in title block; ApprovedBy: Not shown in title block; CheckedBy: Not shown in title block; Author: Not shown in title block; CompanyName: Not shown in title block; Engineer: Not shown in title block; Organization: Not shown in title block; Address1: Not shown in title block; Address2: Not shown in title block; Address3: Not shown in title block; Address4: Not shown in title block; DocumentNumber: 7; Revision: Use project parameter SCH_Rev; SheetNumber: 7; SheetTotal: 11; PageSetup: Record=PageOptions¦CenterHorizontal=True¦CenterVertical=True¦PrintScale=1.00¦XCorrection=1.00¦YCorrection=1.00¦PrintKind=0¦BorderSize=5000000¦LeftOffset=0¦BottomOffset=0¦Orientation=2¦PaperLength=1000¦PaperWidth=1000¦Scale=100¦PaperSource=15¦PrintQuality=600¦MediaType=1¦DitherType=10¦PaperKind=Letter¦PrintScaleMode=1
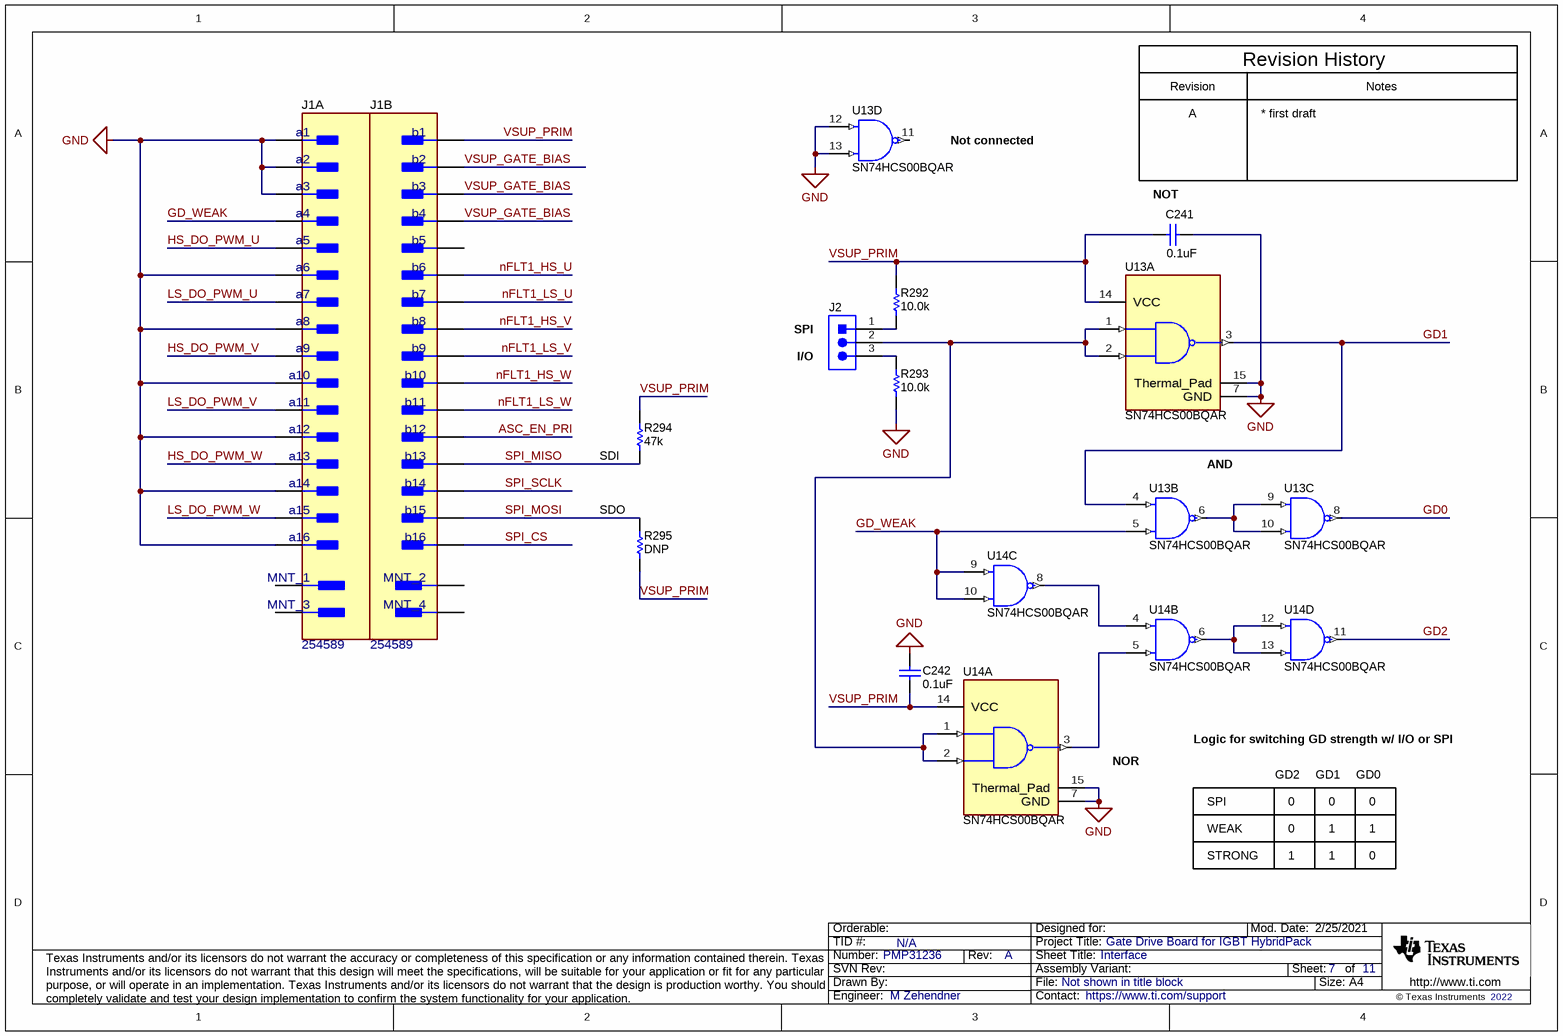
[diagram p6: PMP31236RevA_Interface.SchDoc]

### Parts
C241  ValueDisplayed: 0.1uF  [0402]  (hidden comment: GRM155R71E104KE14D)
C242  ValueDisplayed: 0.1uF  [0402]  (hidden comment: GRM155R71E104KE14D)
J1  254589  [FP-254589_CONN_HDR32-MFG]  (parts A,B of 2)
J2  HTSW-103-09-G-S  [Samtec_HTSW-103-09-x-S]  (value not drawn)
R292  ValueDisplayed: 10.0k  [0402]  (hidden comment: CRCW040210K0FKED)
R293  ValueDisplayed: 10.0k  [0402]  (hidden comment: CRCW040210K0FKED)
R294  ValueDisplayed: 47k  [0402]  (hidden comment: CRCW040247K0JNED)
R295  ValueDisplayed: DNP  [0402]  (hidden comment: CRCW040247K0JNED)
U13  SN74HCS00BQAR  [BQA0014A-MFG]  (parts A,B,C,D of 4)
U14  SN74HCS00BQAR  [BQA0014A-MFG]  (parts A,B,C,D of 4)

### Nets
GND: C241.1 C242.1 J1.a1 J1.a2 J1.a3 J1.a6 J1.a8 J1.a10 J1.a12 J1.a14 J1.a16 R293.1 U13.7(GND) U13.12(4A) U13.13(4B) U13.15(Thermal_Pad) U14.7(GND) U14.15(Thermal_Pad)
ASC_EN_PRI: J1.b12
GD0: U13.8(3Y)
GD1: U13.3(1Y) U13.4(2A)
GD2: U14.11(4Y)
GD_WEAK: J1.a4 U13.5(2B) U14.9(3A) U14.10(3B)
HS_DO_PWM_U: J1.a5
HS_DO_PWM_V: J1.a9
HS_DO_PWM_W: J1.a13
LS_DO_PWM_U: J1.a7
LS_DO_PWM_V: J1.a11
LS_DO_PWM_W: J1.a15
nFLT1_HS_U: J1.b6
nFLT1_HS_V: J1.b8
nFLT1_HS_W: J1.b10
nFLT1_LS_U: J1.b7
nFLT1_LS_V: J1.b9
nFLT1_LS_W: J1.b11
SPI_CS: J1.b16
SPI_MISO: J1.b13 R294.1
SPI_MOSI: J1.b15 R295.2
SPI_SCLK: J1.b14
VSUP_GATE_BIAS: J1.b2 J1.b3 J1.b4
VSUP_PRIM: C241.2 C242.2 J1.b1 R292.2 R294.2 R295.1 U13.14(VCC) U14.14(VCC)
NetJ2_1: J2.1 R292.1
NetJ2_2: J2.2 U13.1(1A) U13.2(1B) U14.1(1A) U14.2(1B)
NetJ2_3: J2.3 R293.2
NetU13_6: U13.6(2Y) U13.9(3A) U13.10(3B)
NetU14_3: U14.3(1Y) U14.5(2B)
NetU14_4: U14.4(2A) U14.8(3Y)
NetU14_6: U14.6(2Y) U14.12(4A) U14.13(4B)

Not connected (* = marked no-connect by the designer): J1 1(MNT_1) 2(MNT_2) 3(MNT_3) 4(MNT_4) b5; U13 11(4Y)

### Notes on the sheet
- Revision
- A
- * first draft
- Revision History
- Notes
- (near U13) Not connected
- (near C241) NOT
- (near J2) SPI
- (near J2) I/O
- (near R295) SDO
- (near R294) SDI
- (near U13) AND
- (near U14) NOR
- Logic for switching GD strength w/ I/O or SPI
- GD2
- GD1
- GD0
- WEAK
- STRONG
- SPI
- 0
- 1

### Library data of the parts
C241 C242 = CMP-0006659-2: CAP, CERM, 0.1 uF, 25 V, +/- 10%, X7R, 0402; Manufacturer: MuRata; TaMin_C: -55°C; Polarized: N; SizeAreaWB_mm2: 3; Value1: Unknown; U/M: EA; Value: 0.1uF; TaMax_C: 125°C; SizeZ_mm: 0.6; SizeX_mm: 1; SizeY_mm: 0.5; Value2: 25V; Cap_F: 100nF; AEC Category: Q200
J1 = CMP-0098102-2: Manufacturer: TE Connectivity Erni; Conn Gender: Male; Current_A: 1.7A; AEC Qualified: No; Conn Orientation: Vertical; ContactFinish: Gold; Row_Count: 2; DUT-Pitch_mm: 1.27mm; SizeZ_mm: 6.75mm
J2 = CMP-0075627-1: Header, 100mil, 3x1, Gold, TH; Manufacturer: Samtec; Pitch_mm: 2.54; Gender: Male; Cert_CSA: Y; CT: False; Row_Count: 1
R292 R293 = CMP-0025958-3: as R131 on sheet PMP31236RevA_LS_U
R294 R295 = CMP-0026935-3: as R116 on sheet PMP31236RevA_LS_U
U13 U14 = CMP-0092719-1: NAND Gate IC 4 Channel Schmitt Trigger Input 14-WQFN (3x2.5); Manufacturer: Texas Instruments; Min Supply Voltage: 2V; TaMin_C: -55°C; Propagation Delay: 5ns; PositionCount: 4; TJmax_C: +150°C; SizeZ_mm: 0.8mm; Max Supply Voltage: 6V; Number Of Outputs: 1; TaMax_C: +125°C; Number Of Inputs: 2; Nominal Supply Current: 0.1uA; Standoff Height: 0mm; AEC Qualified: No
